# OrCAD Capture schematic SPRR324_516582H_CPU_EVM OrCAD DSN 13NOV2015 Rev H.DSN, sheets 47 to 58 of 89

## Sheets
47 SH54 - DDR3 MEMORY CAPS BANK 2: size B; rev: A
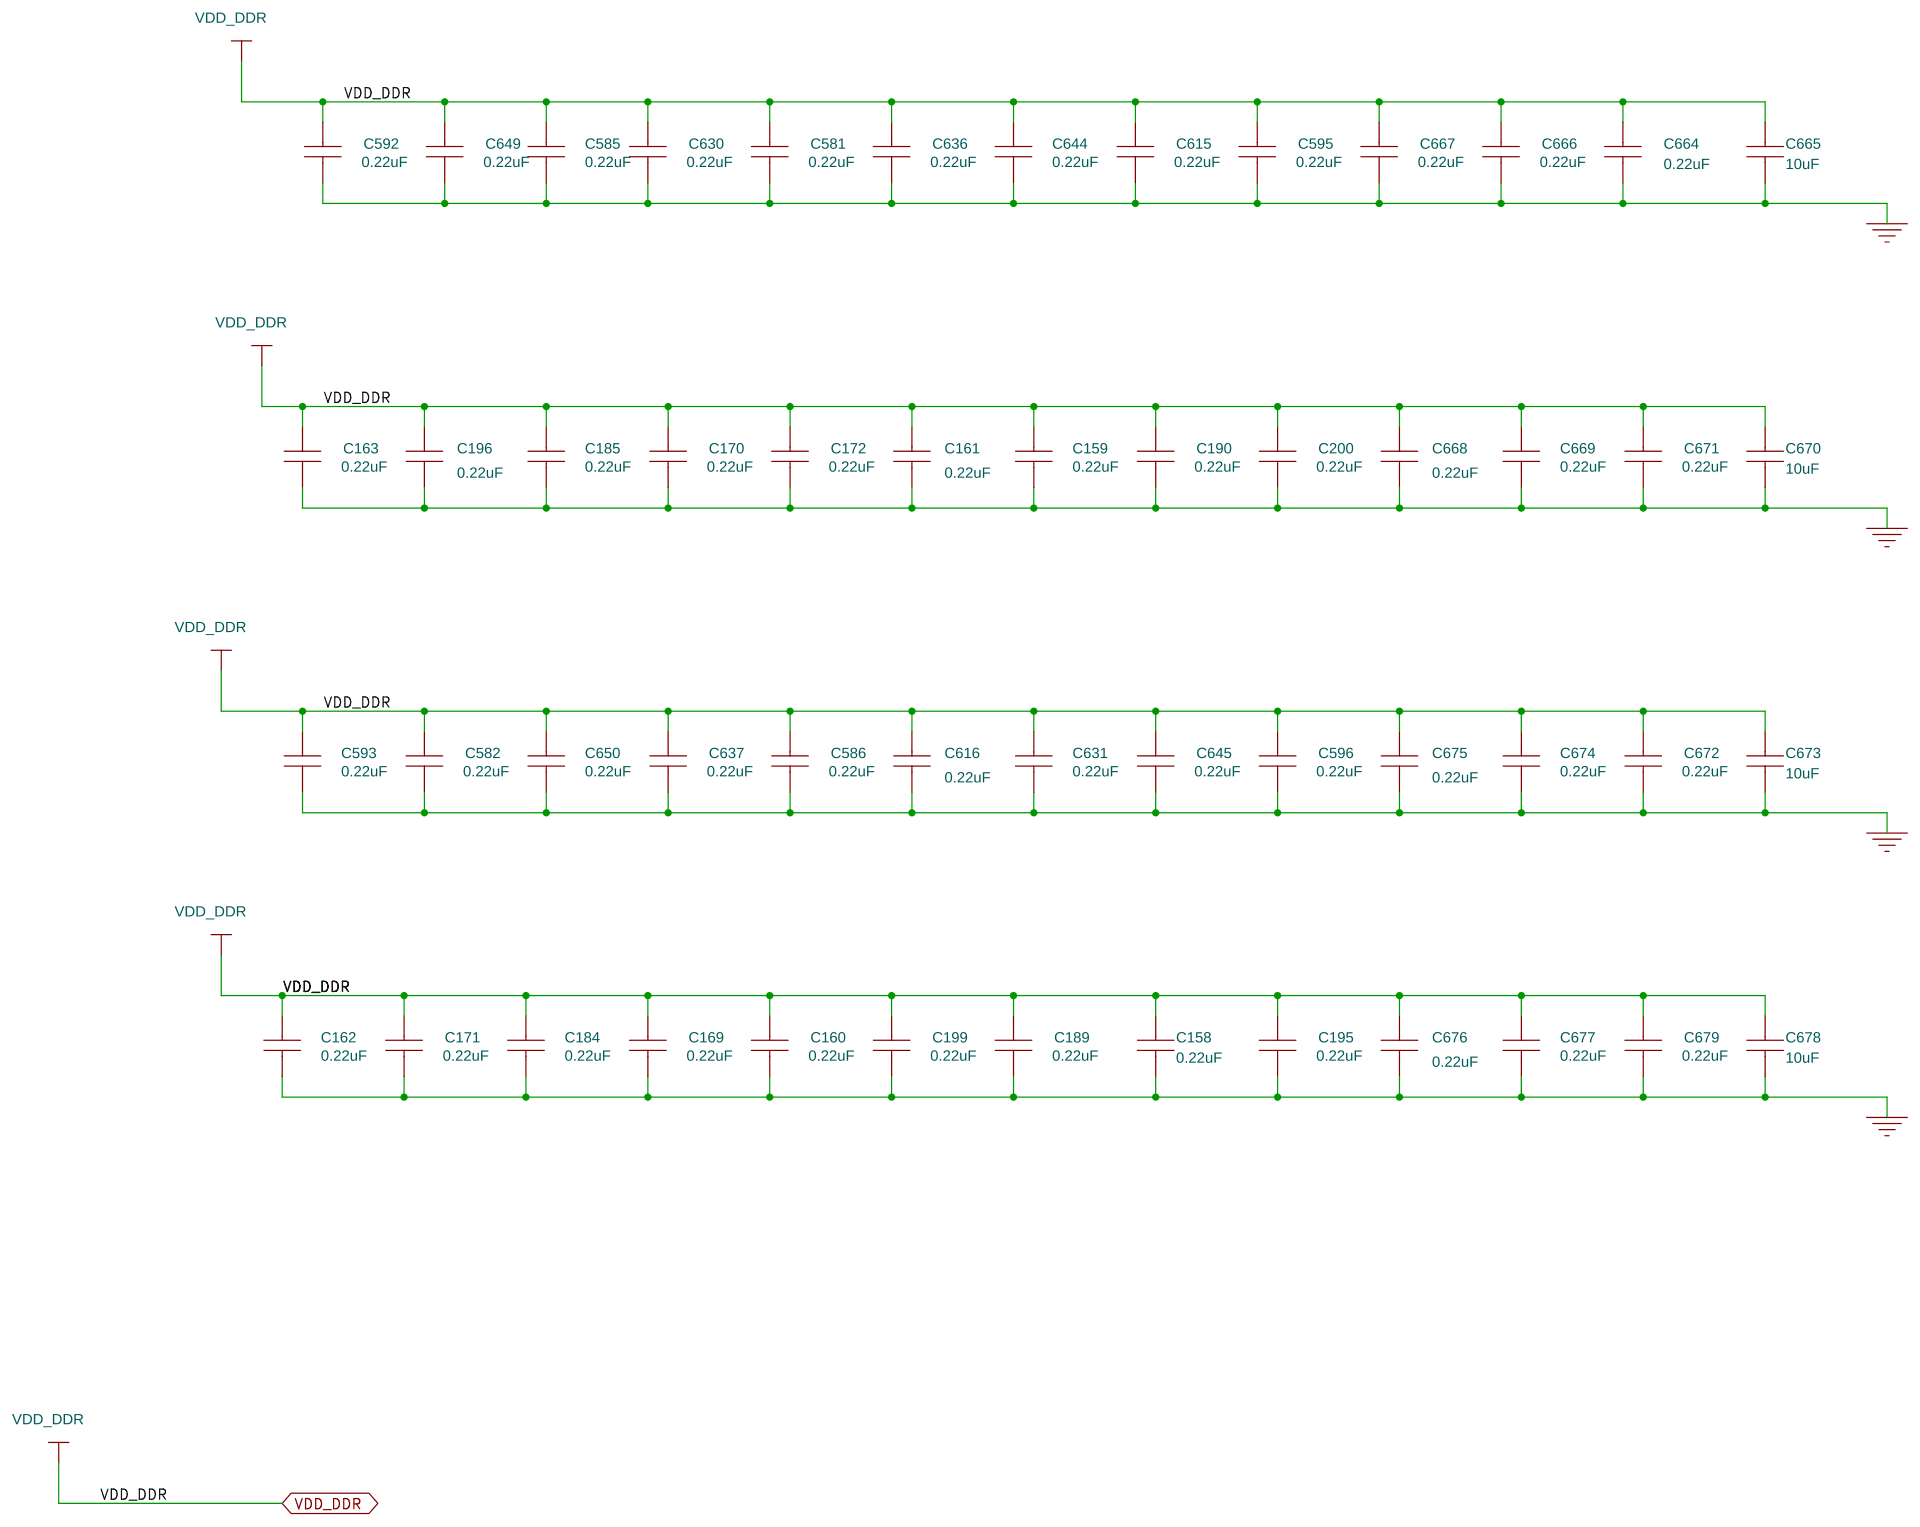
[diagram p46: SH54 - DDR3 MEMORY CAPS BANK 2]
48 SH55 - DDR TERMNATION BANK 2: size B
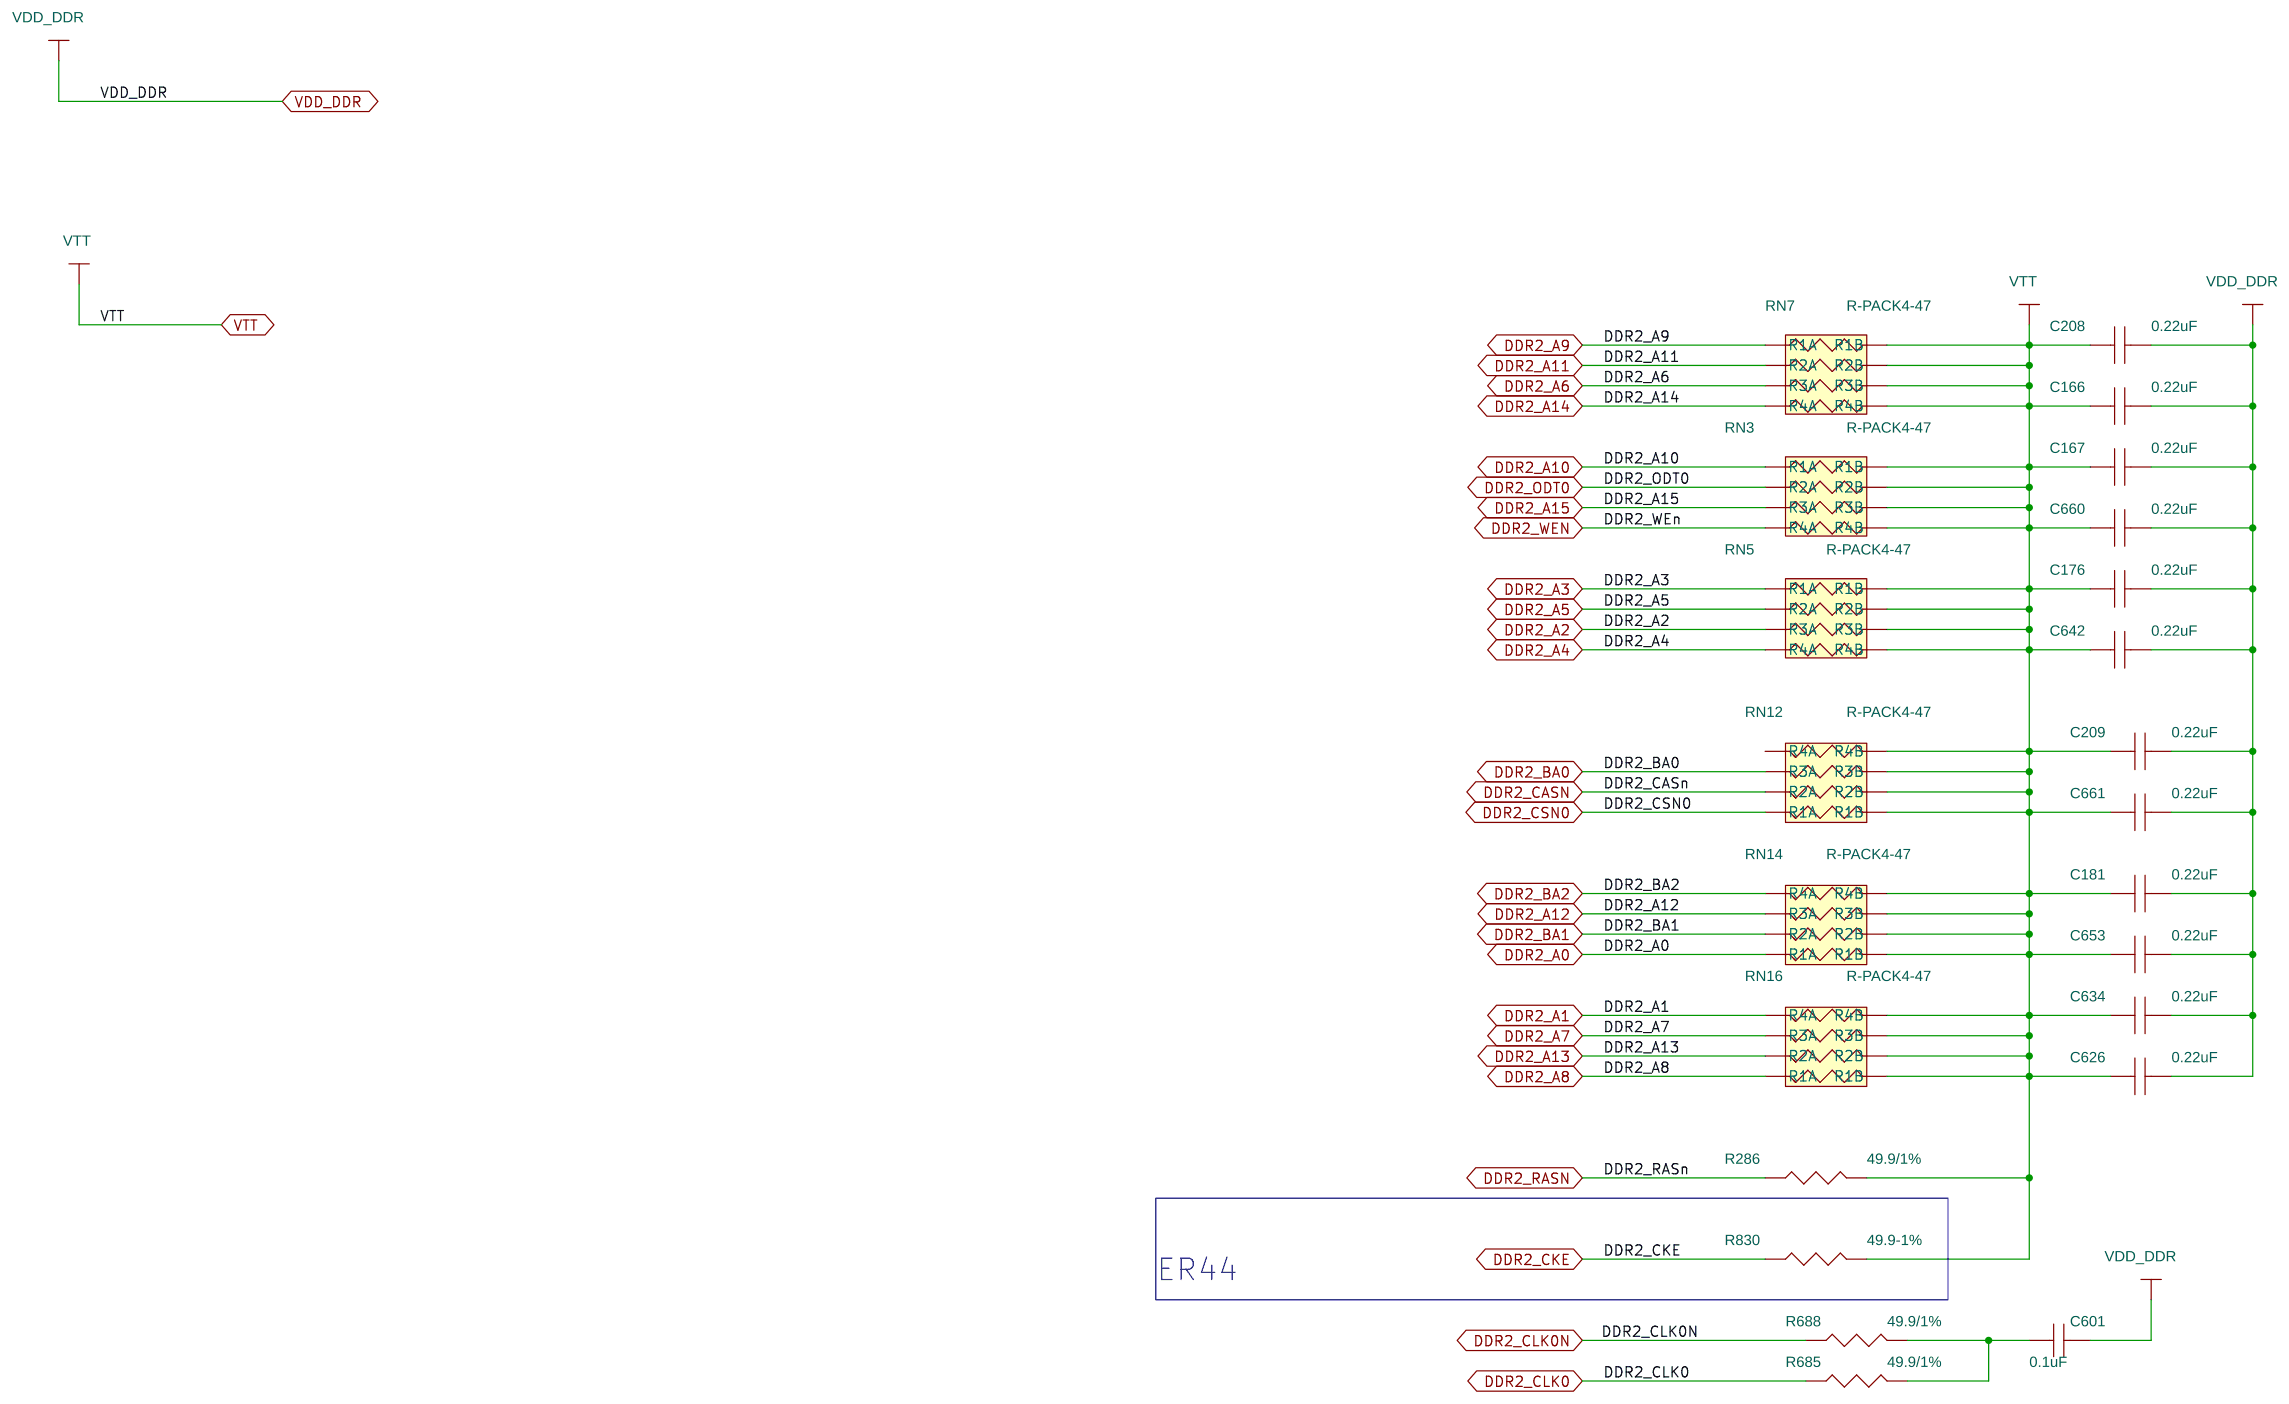
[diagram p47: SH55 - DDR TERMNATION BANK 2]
49 SH56 - USB VBUS: size B; rev: C
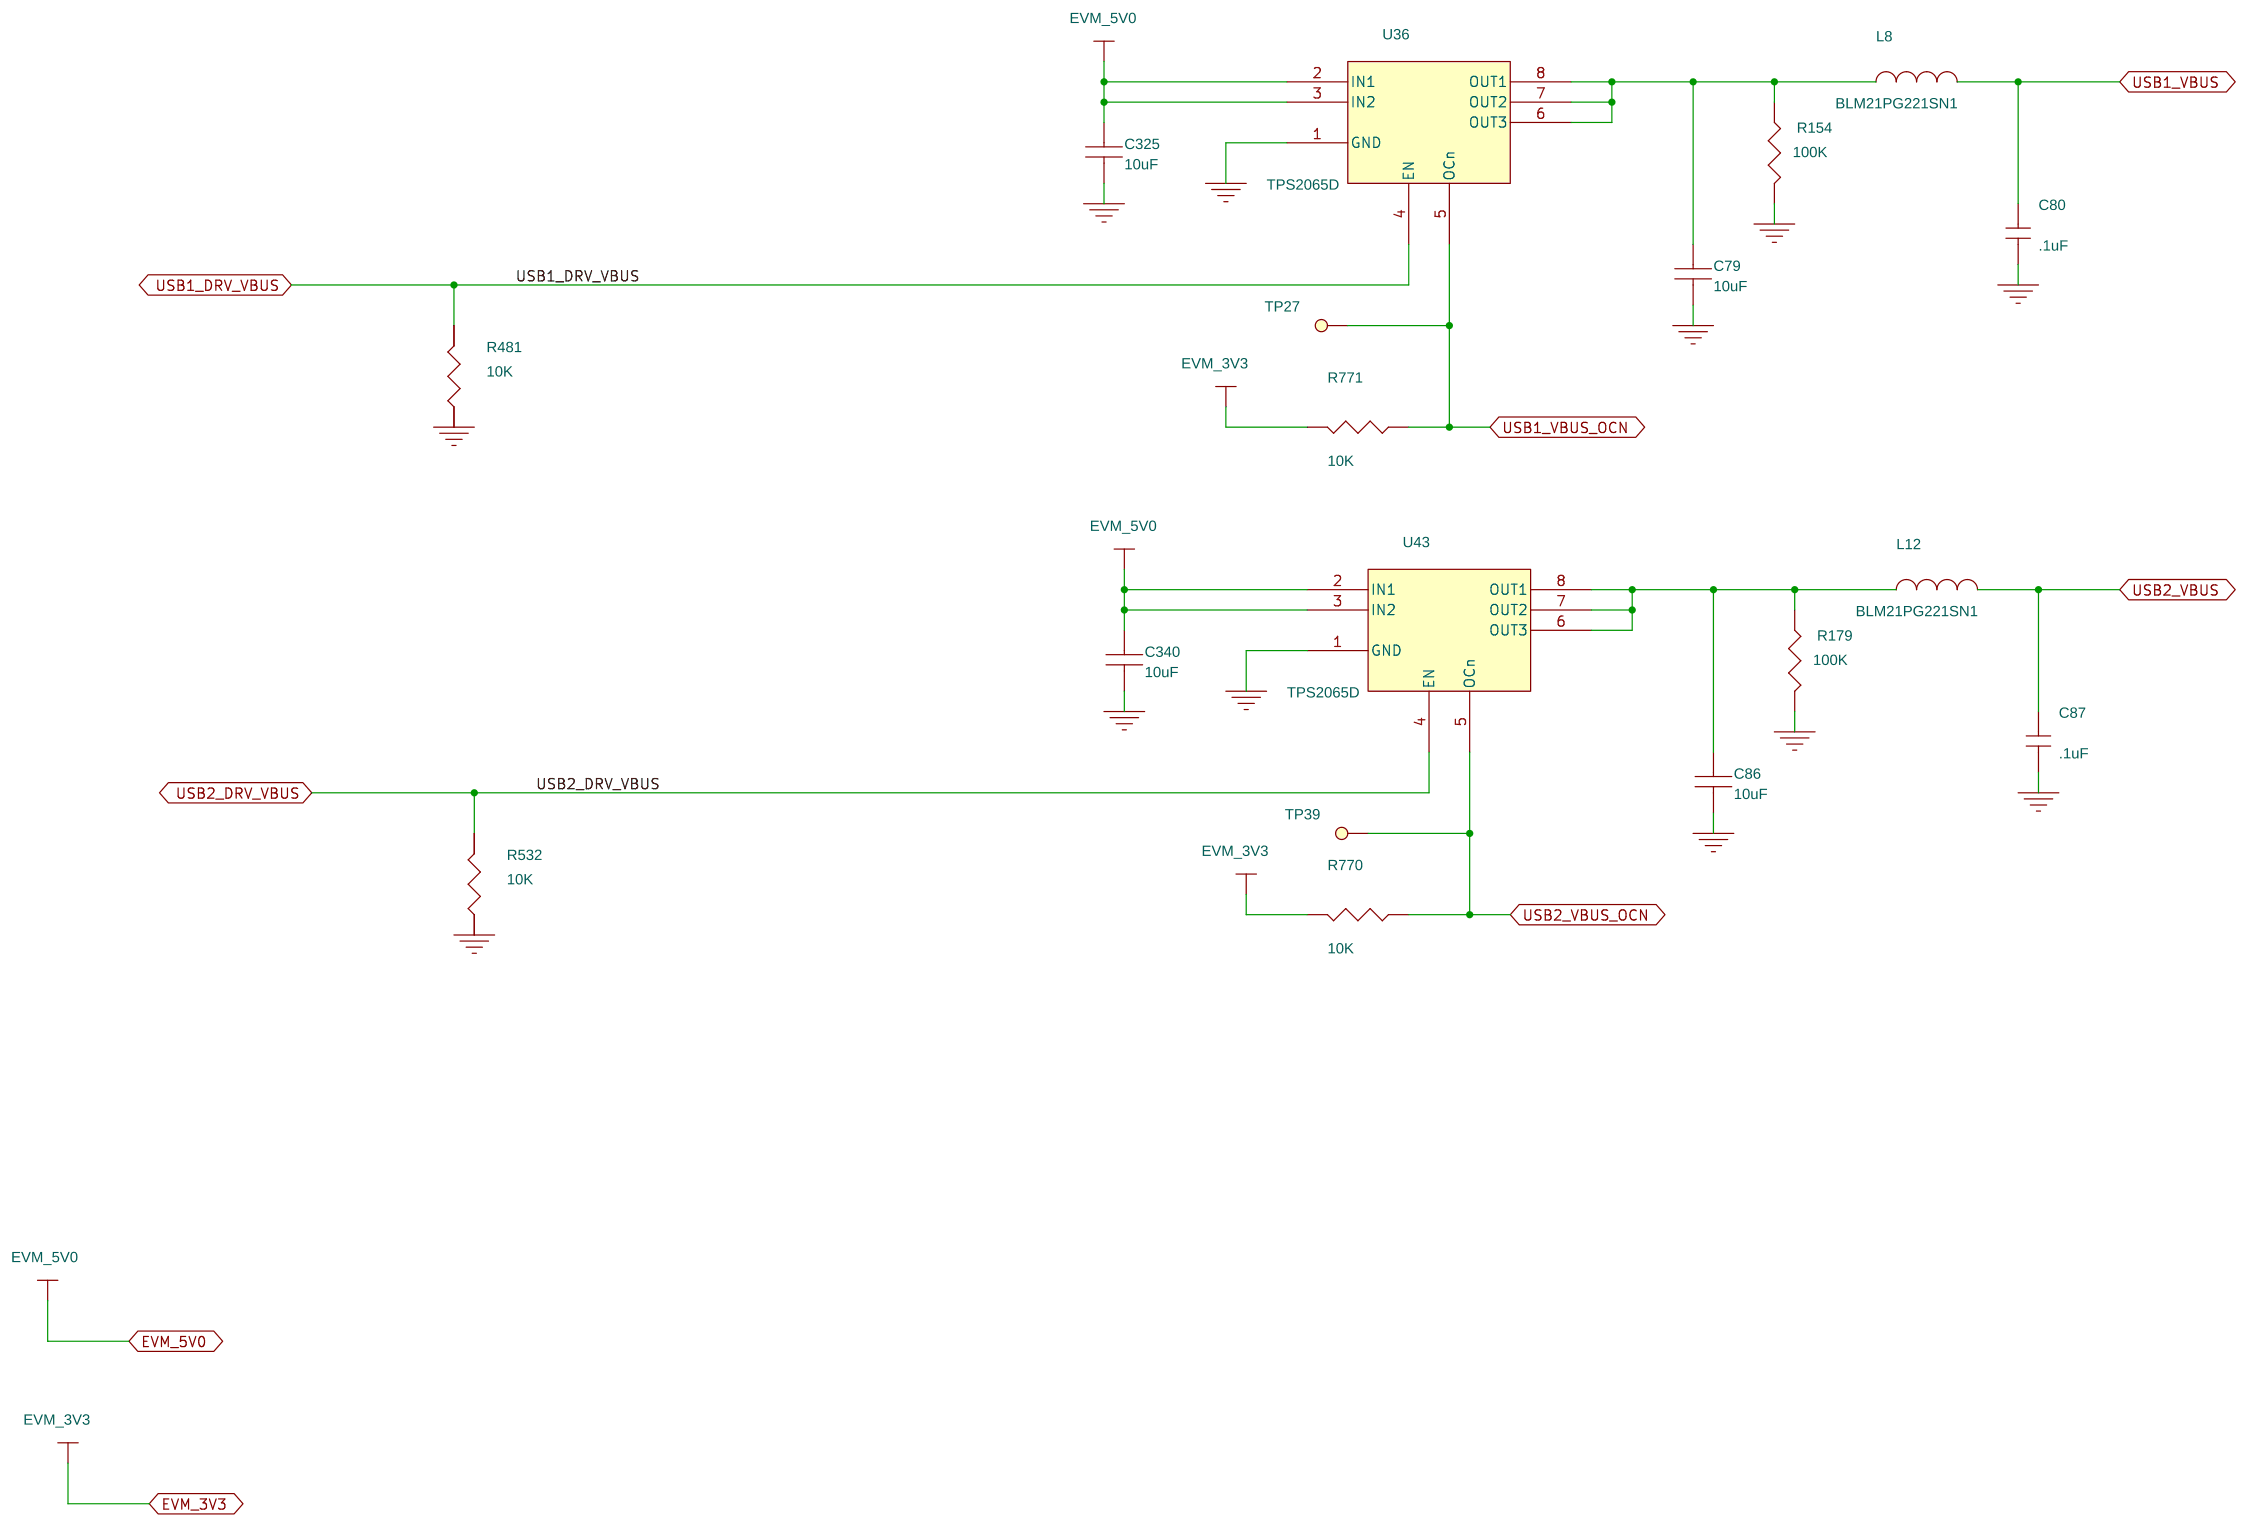
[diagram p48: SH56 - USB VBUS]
50 SH57 - USB CONNECTORS: size B; rev: F
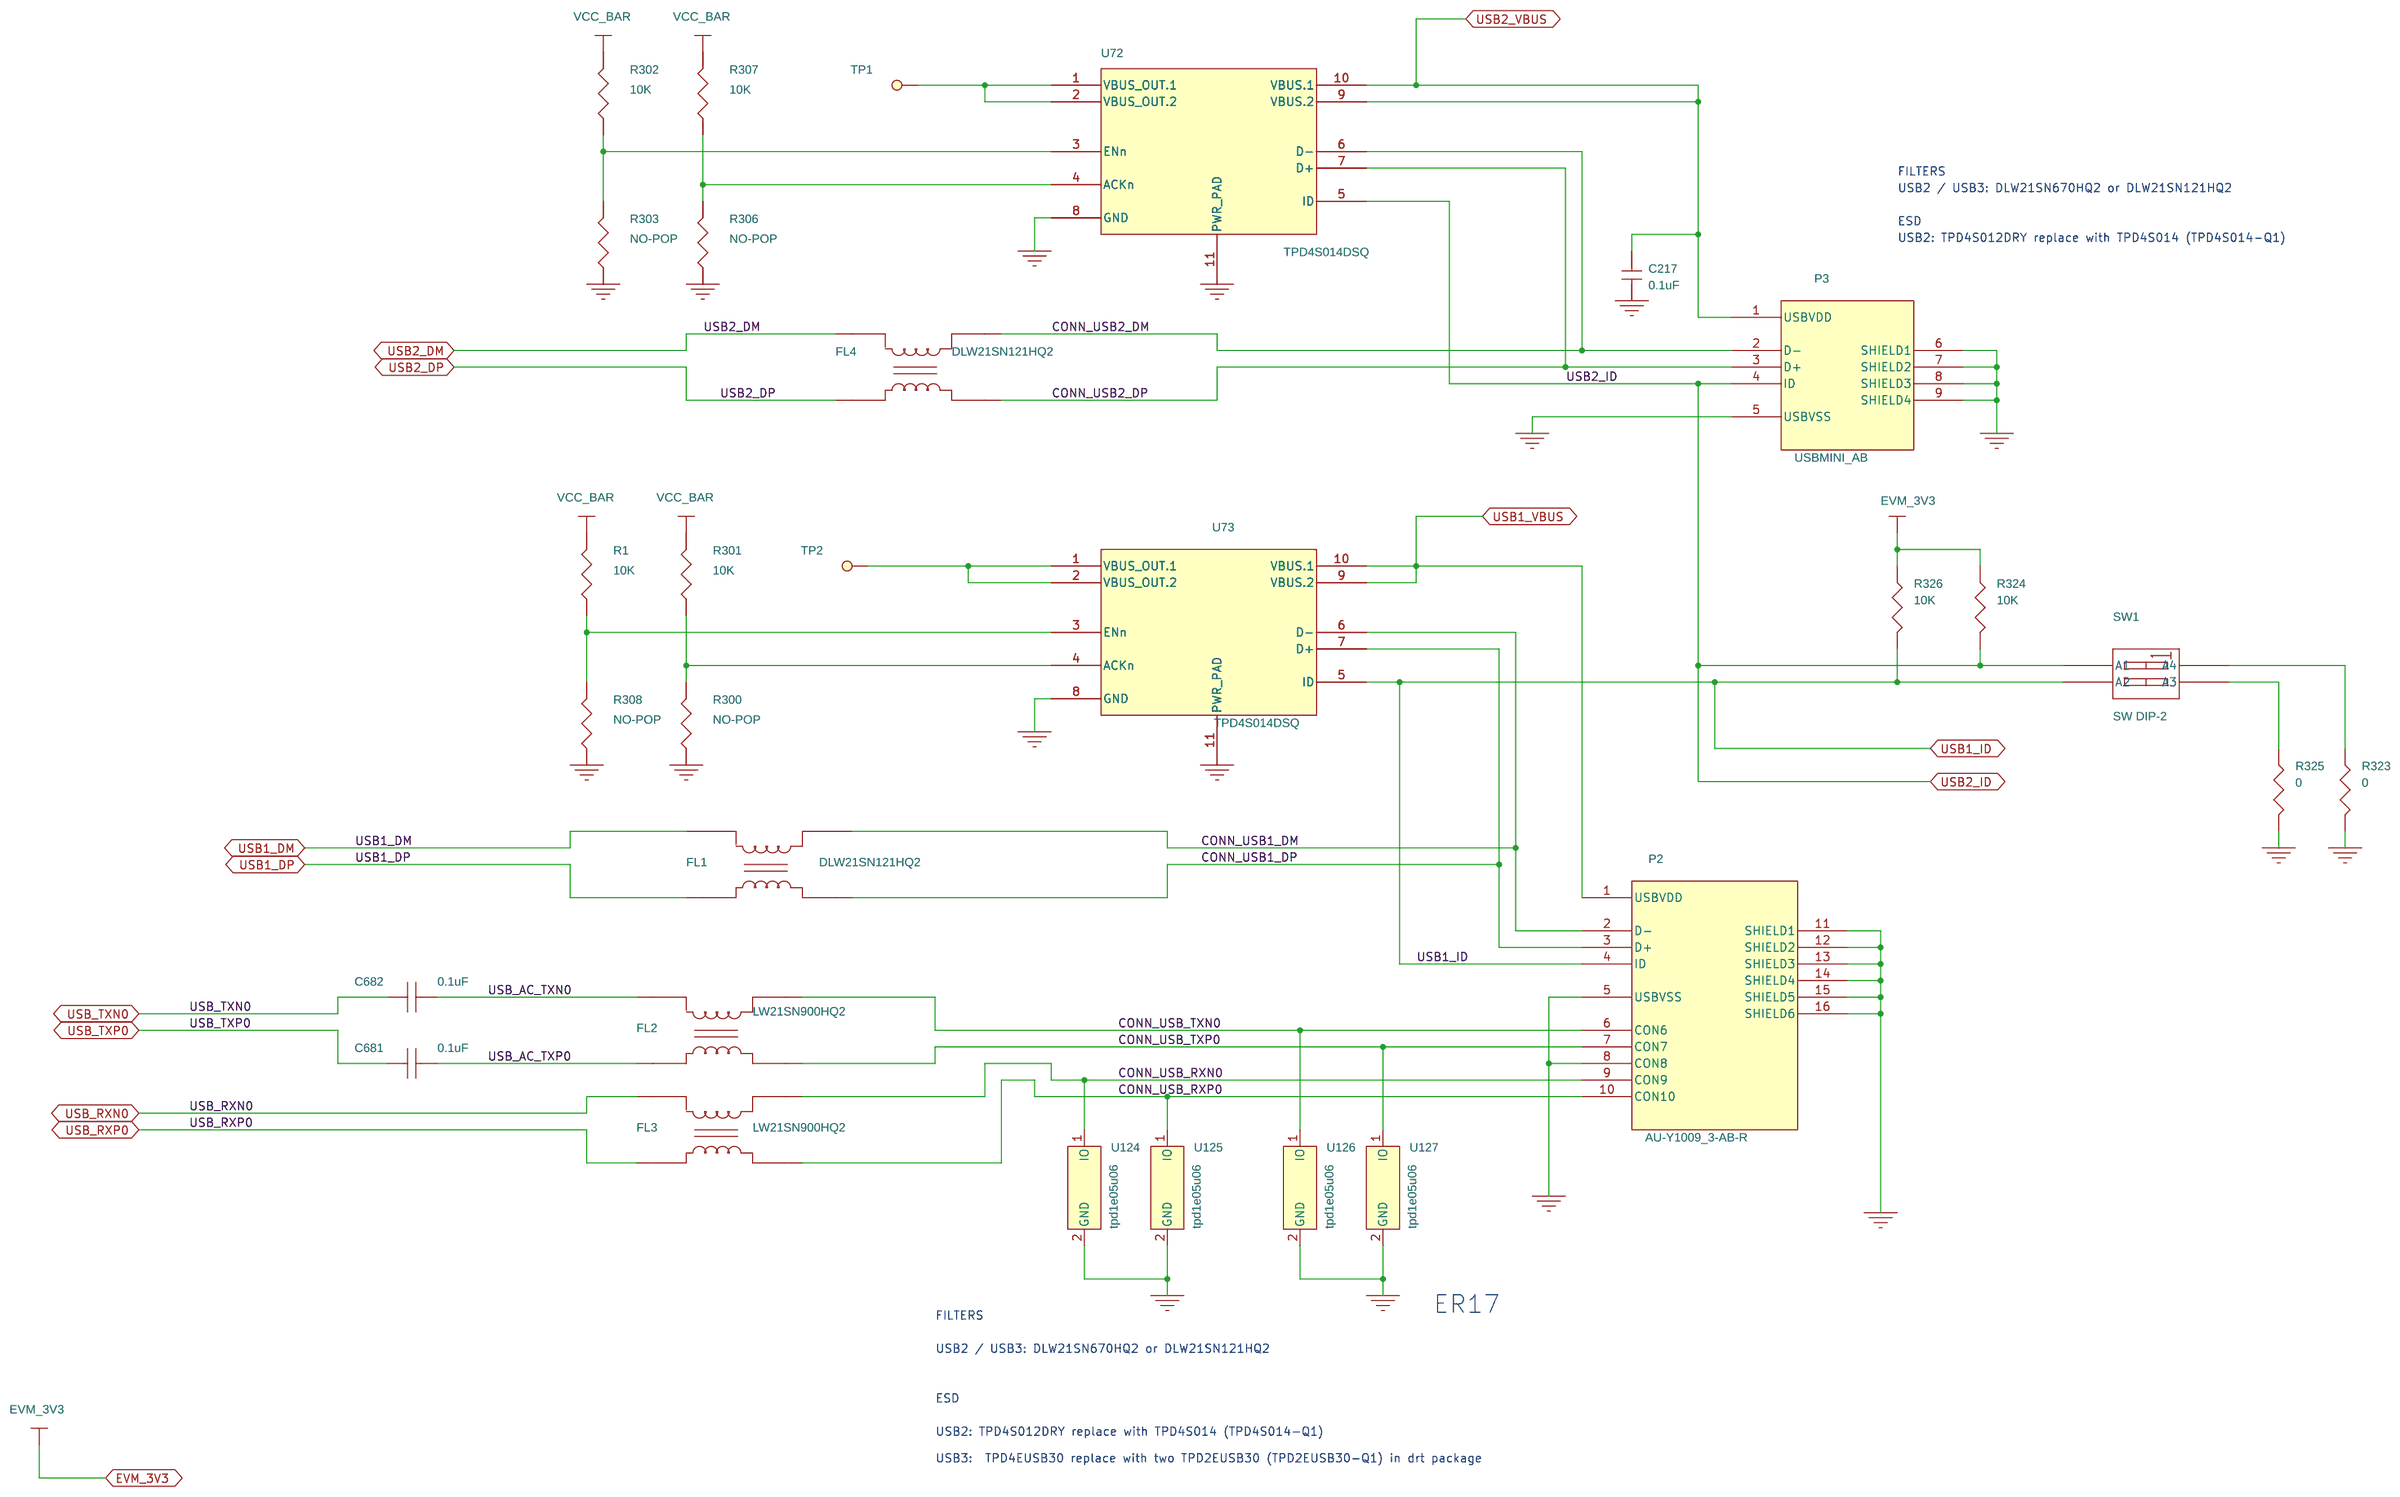
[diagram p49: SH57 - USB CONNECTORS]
51 SH58 - FTDI UART: size B; rev: D
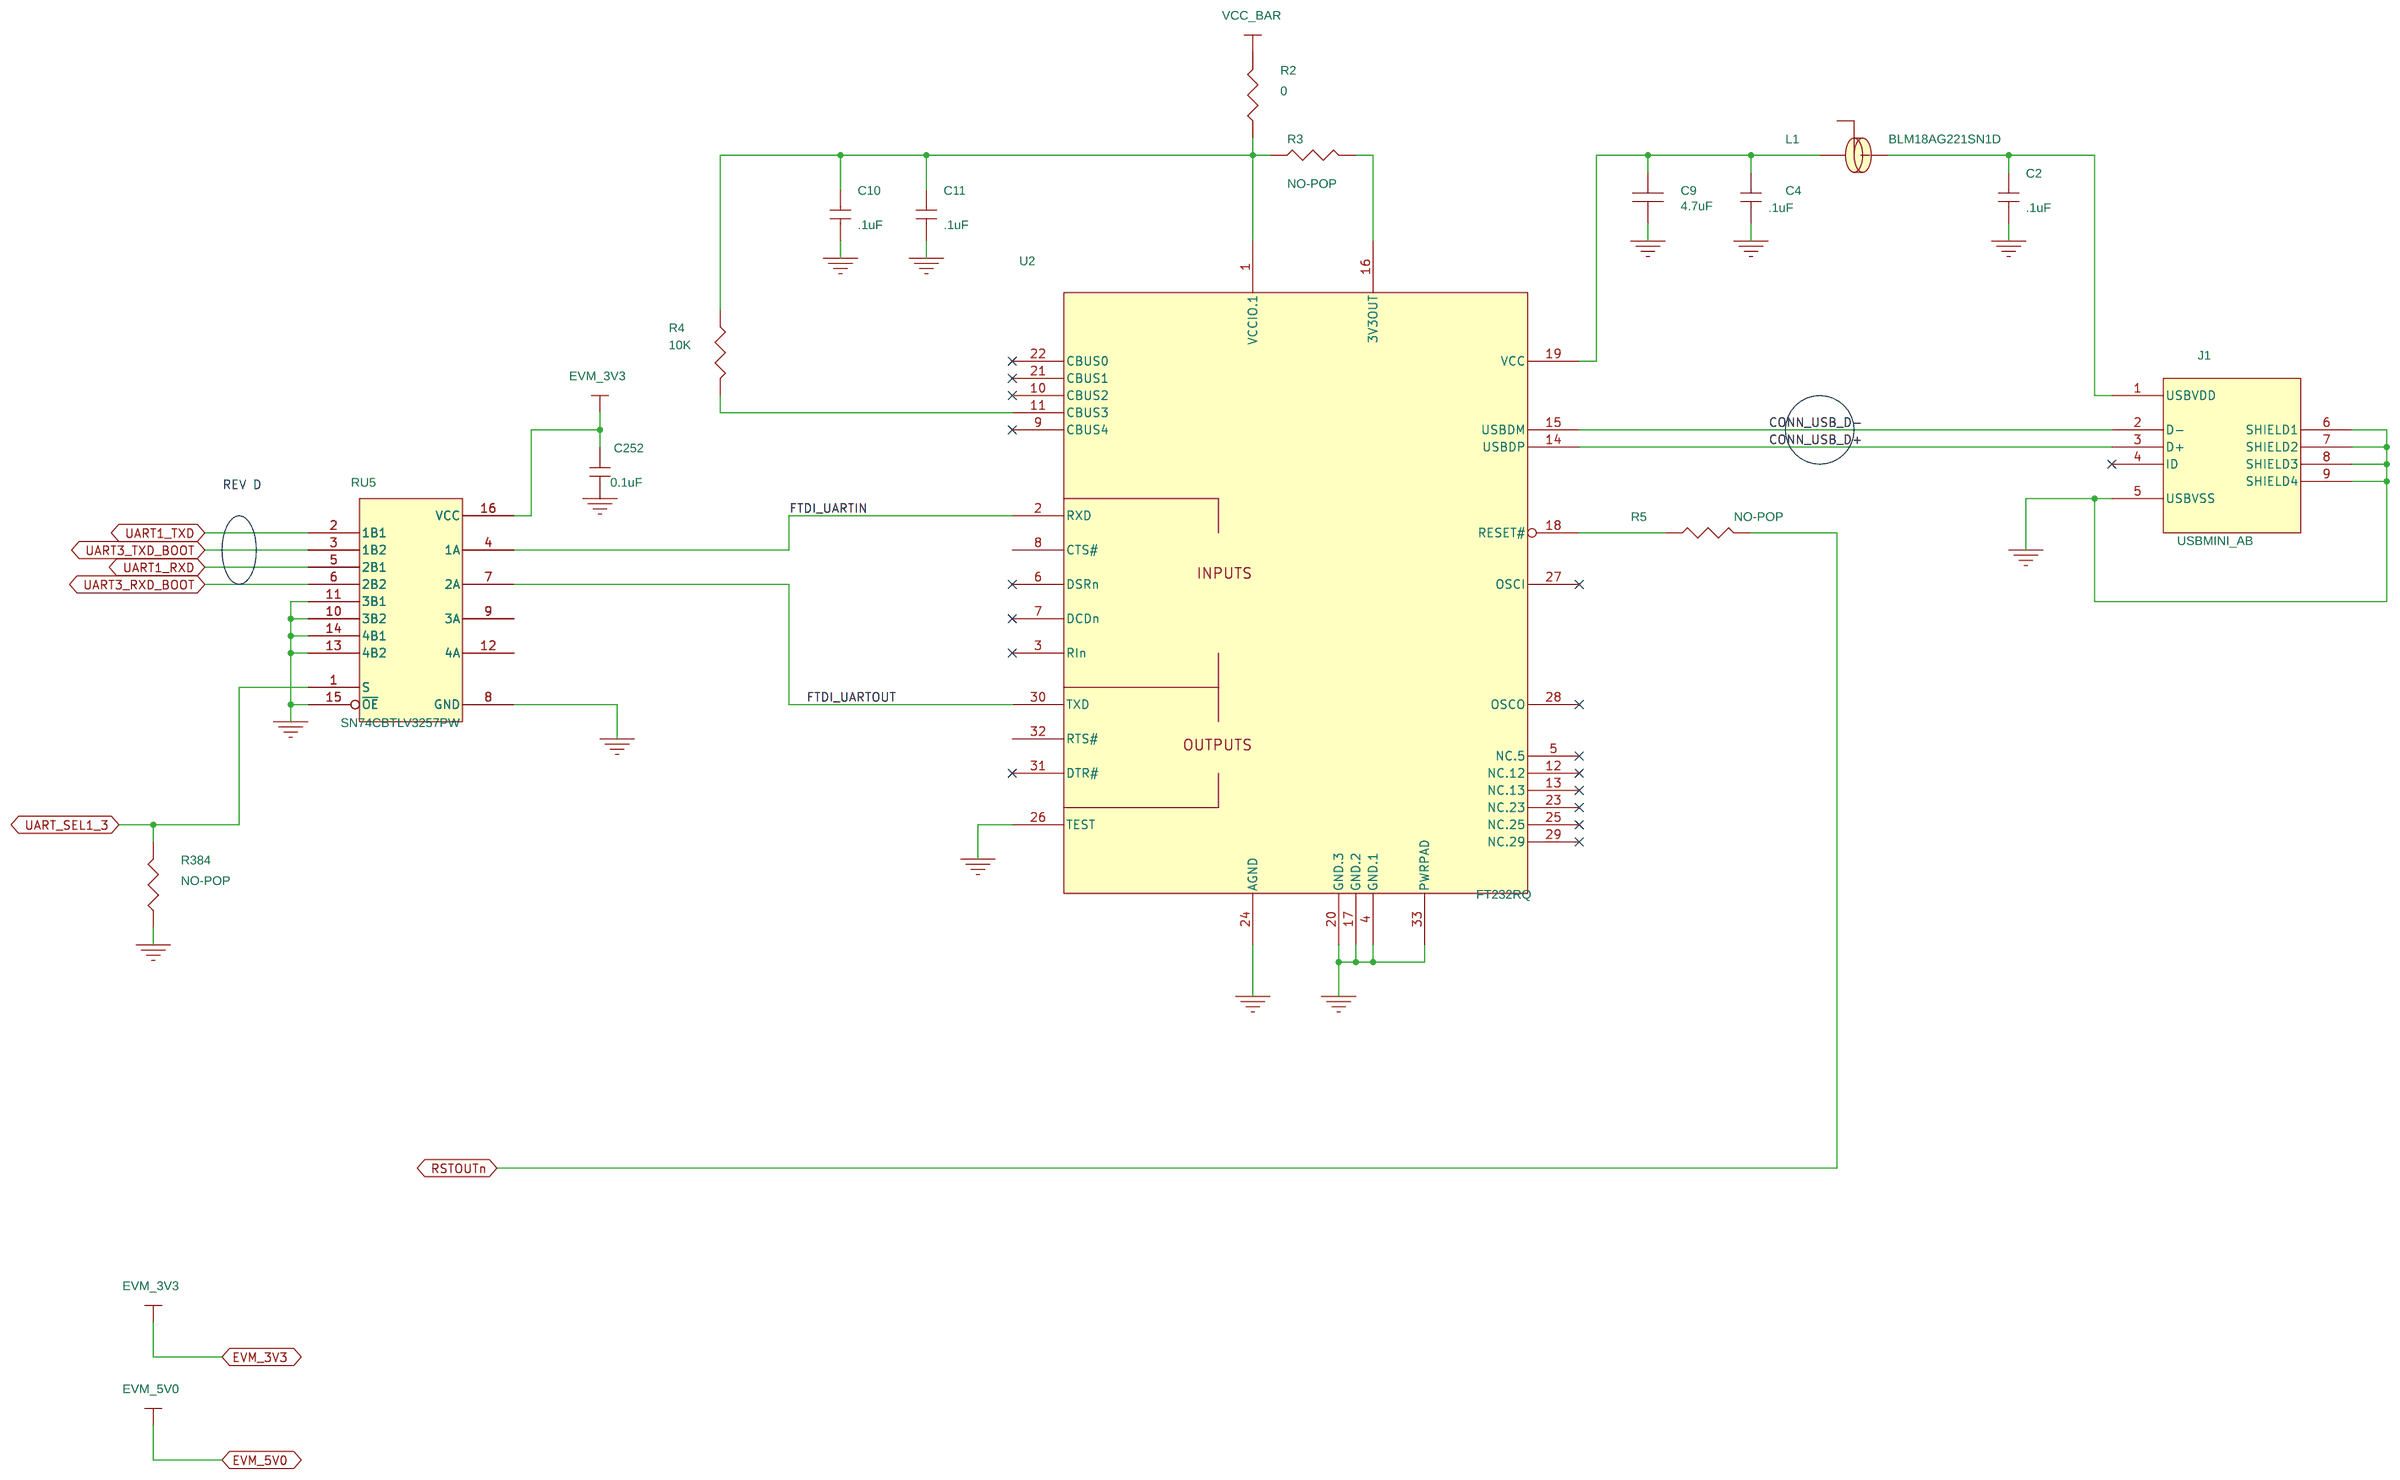
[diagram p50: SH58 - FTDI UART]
52 SH59 - COM8 LEVEL TRANSLATOR: size B; rev: A
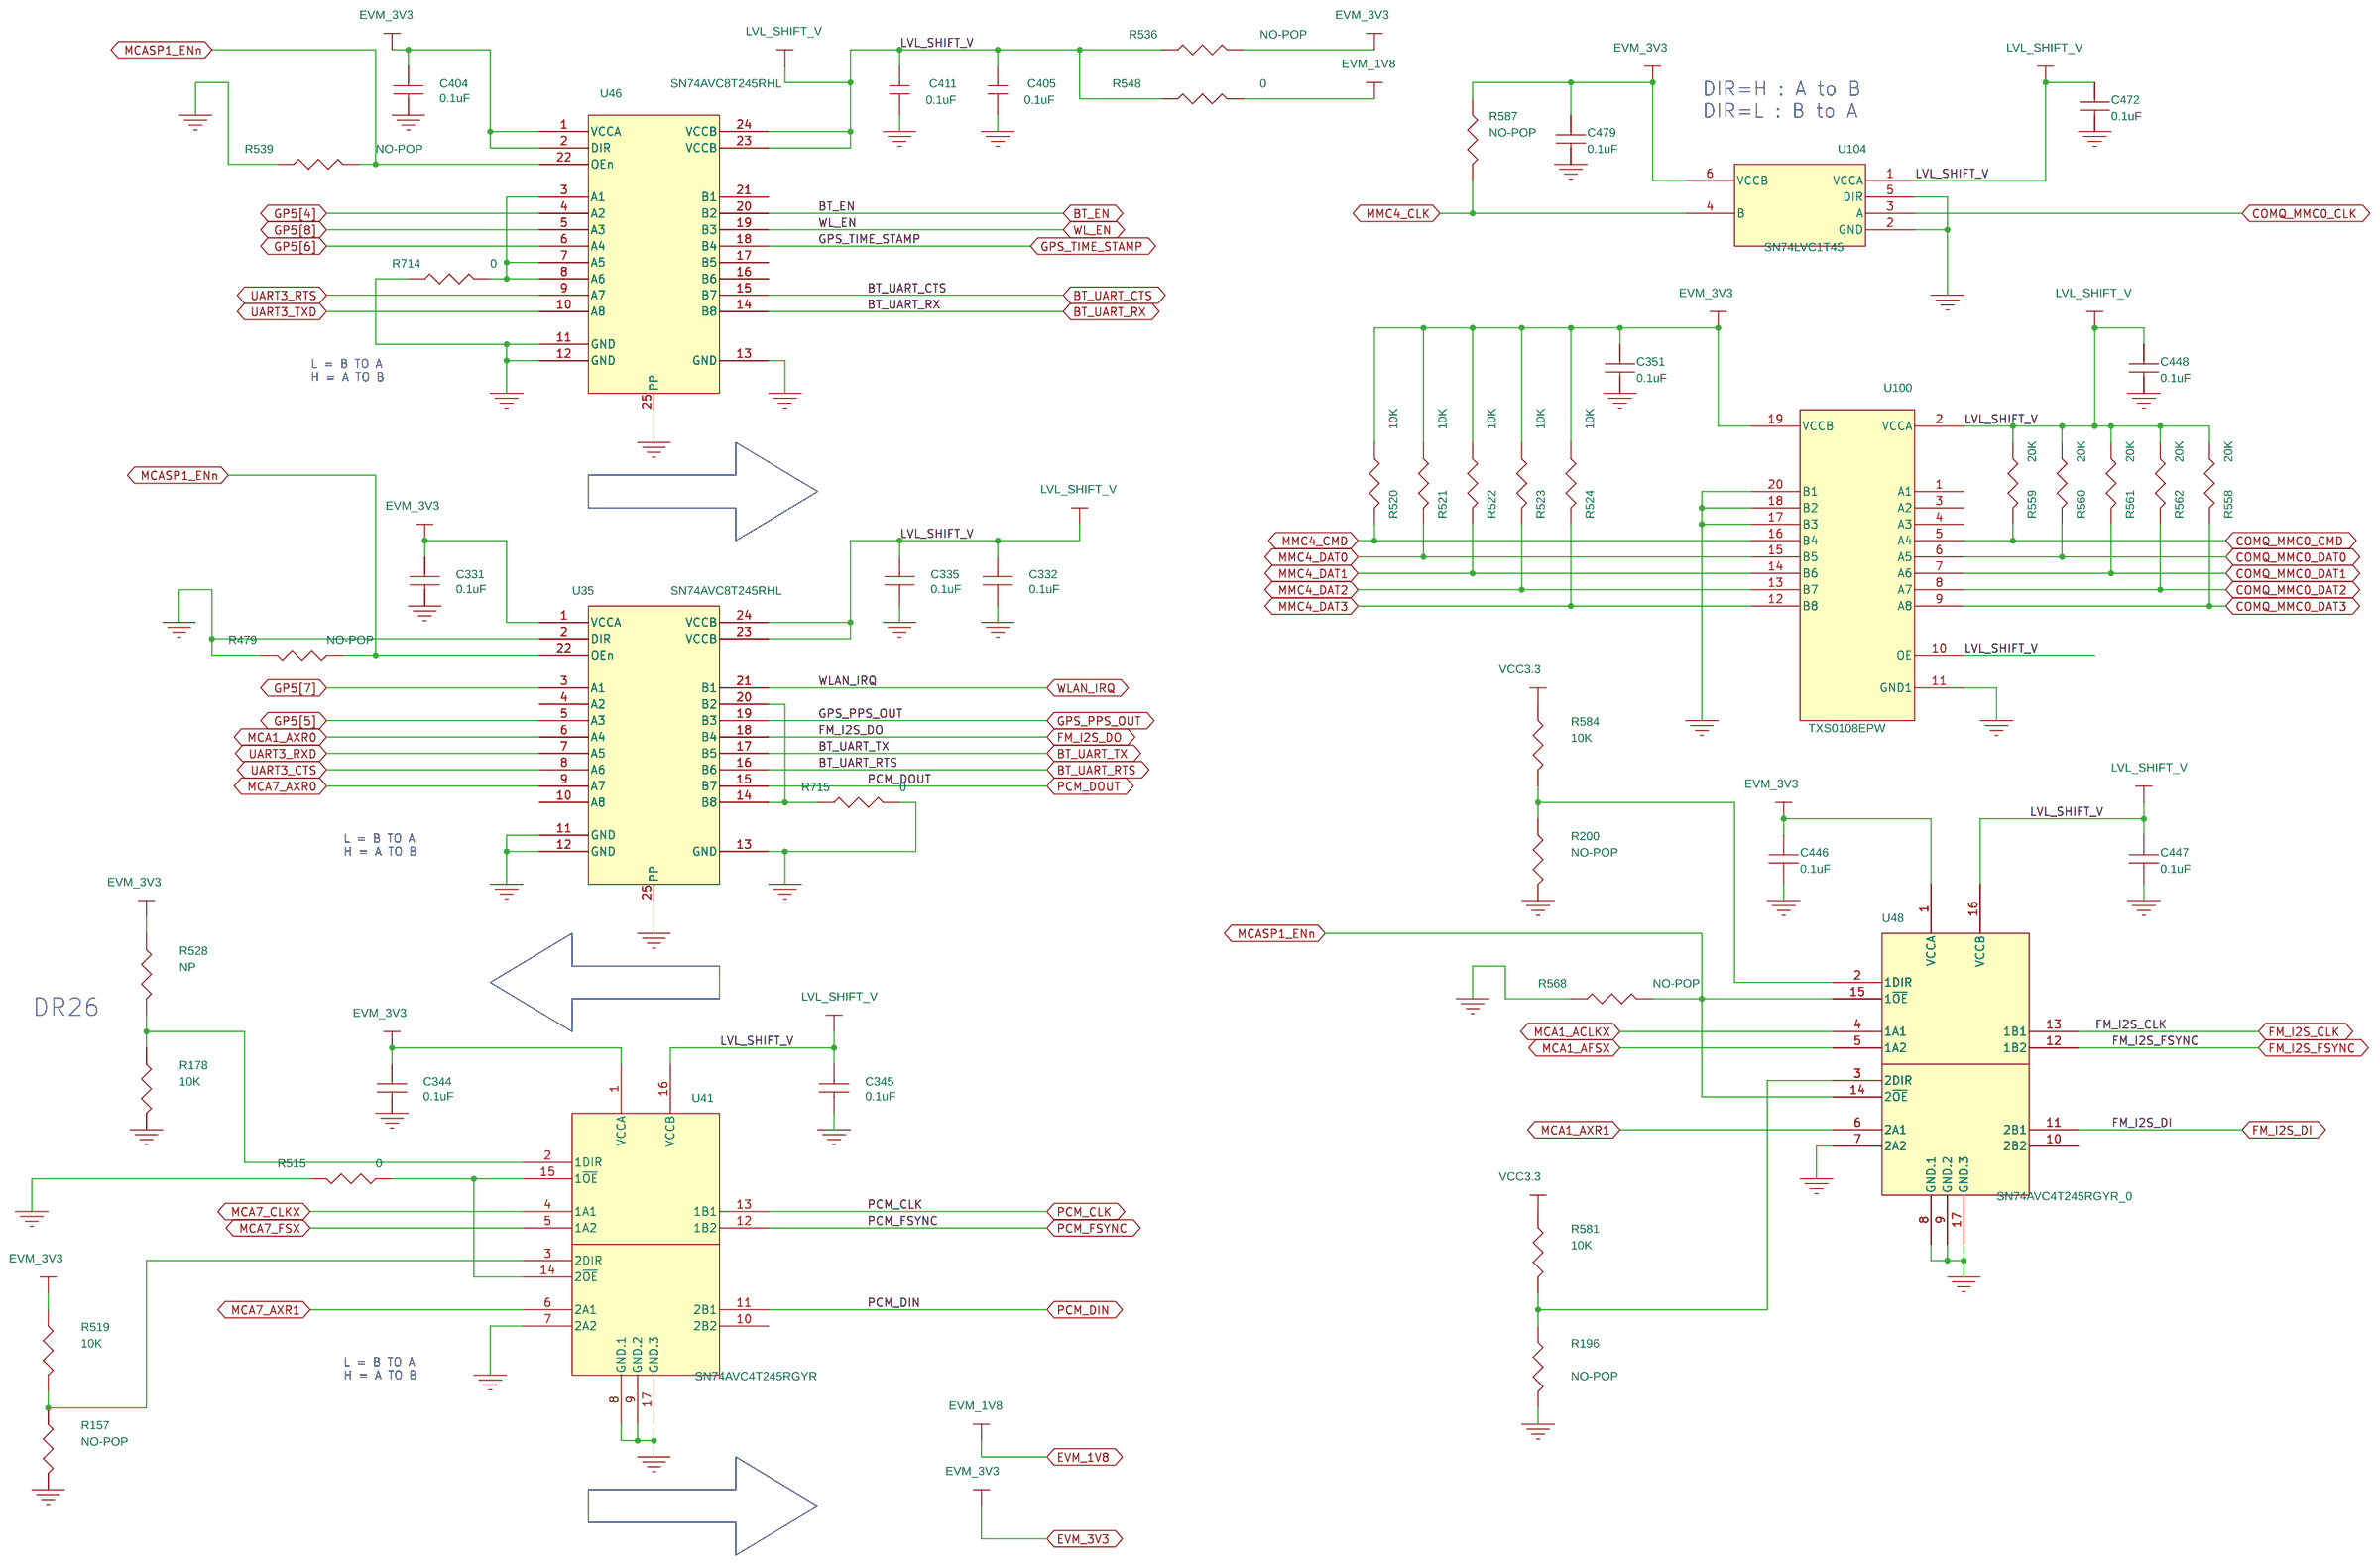
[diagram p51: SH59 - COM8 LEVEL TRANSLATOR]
53 SH60 - COM8 CONNECTOR: size B; rev: A
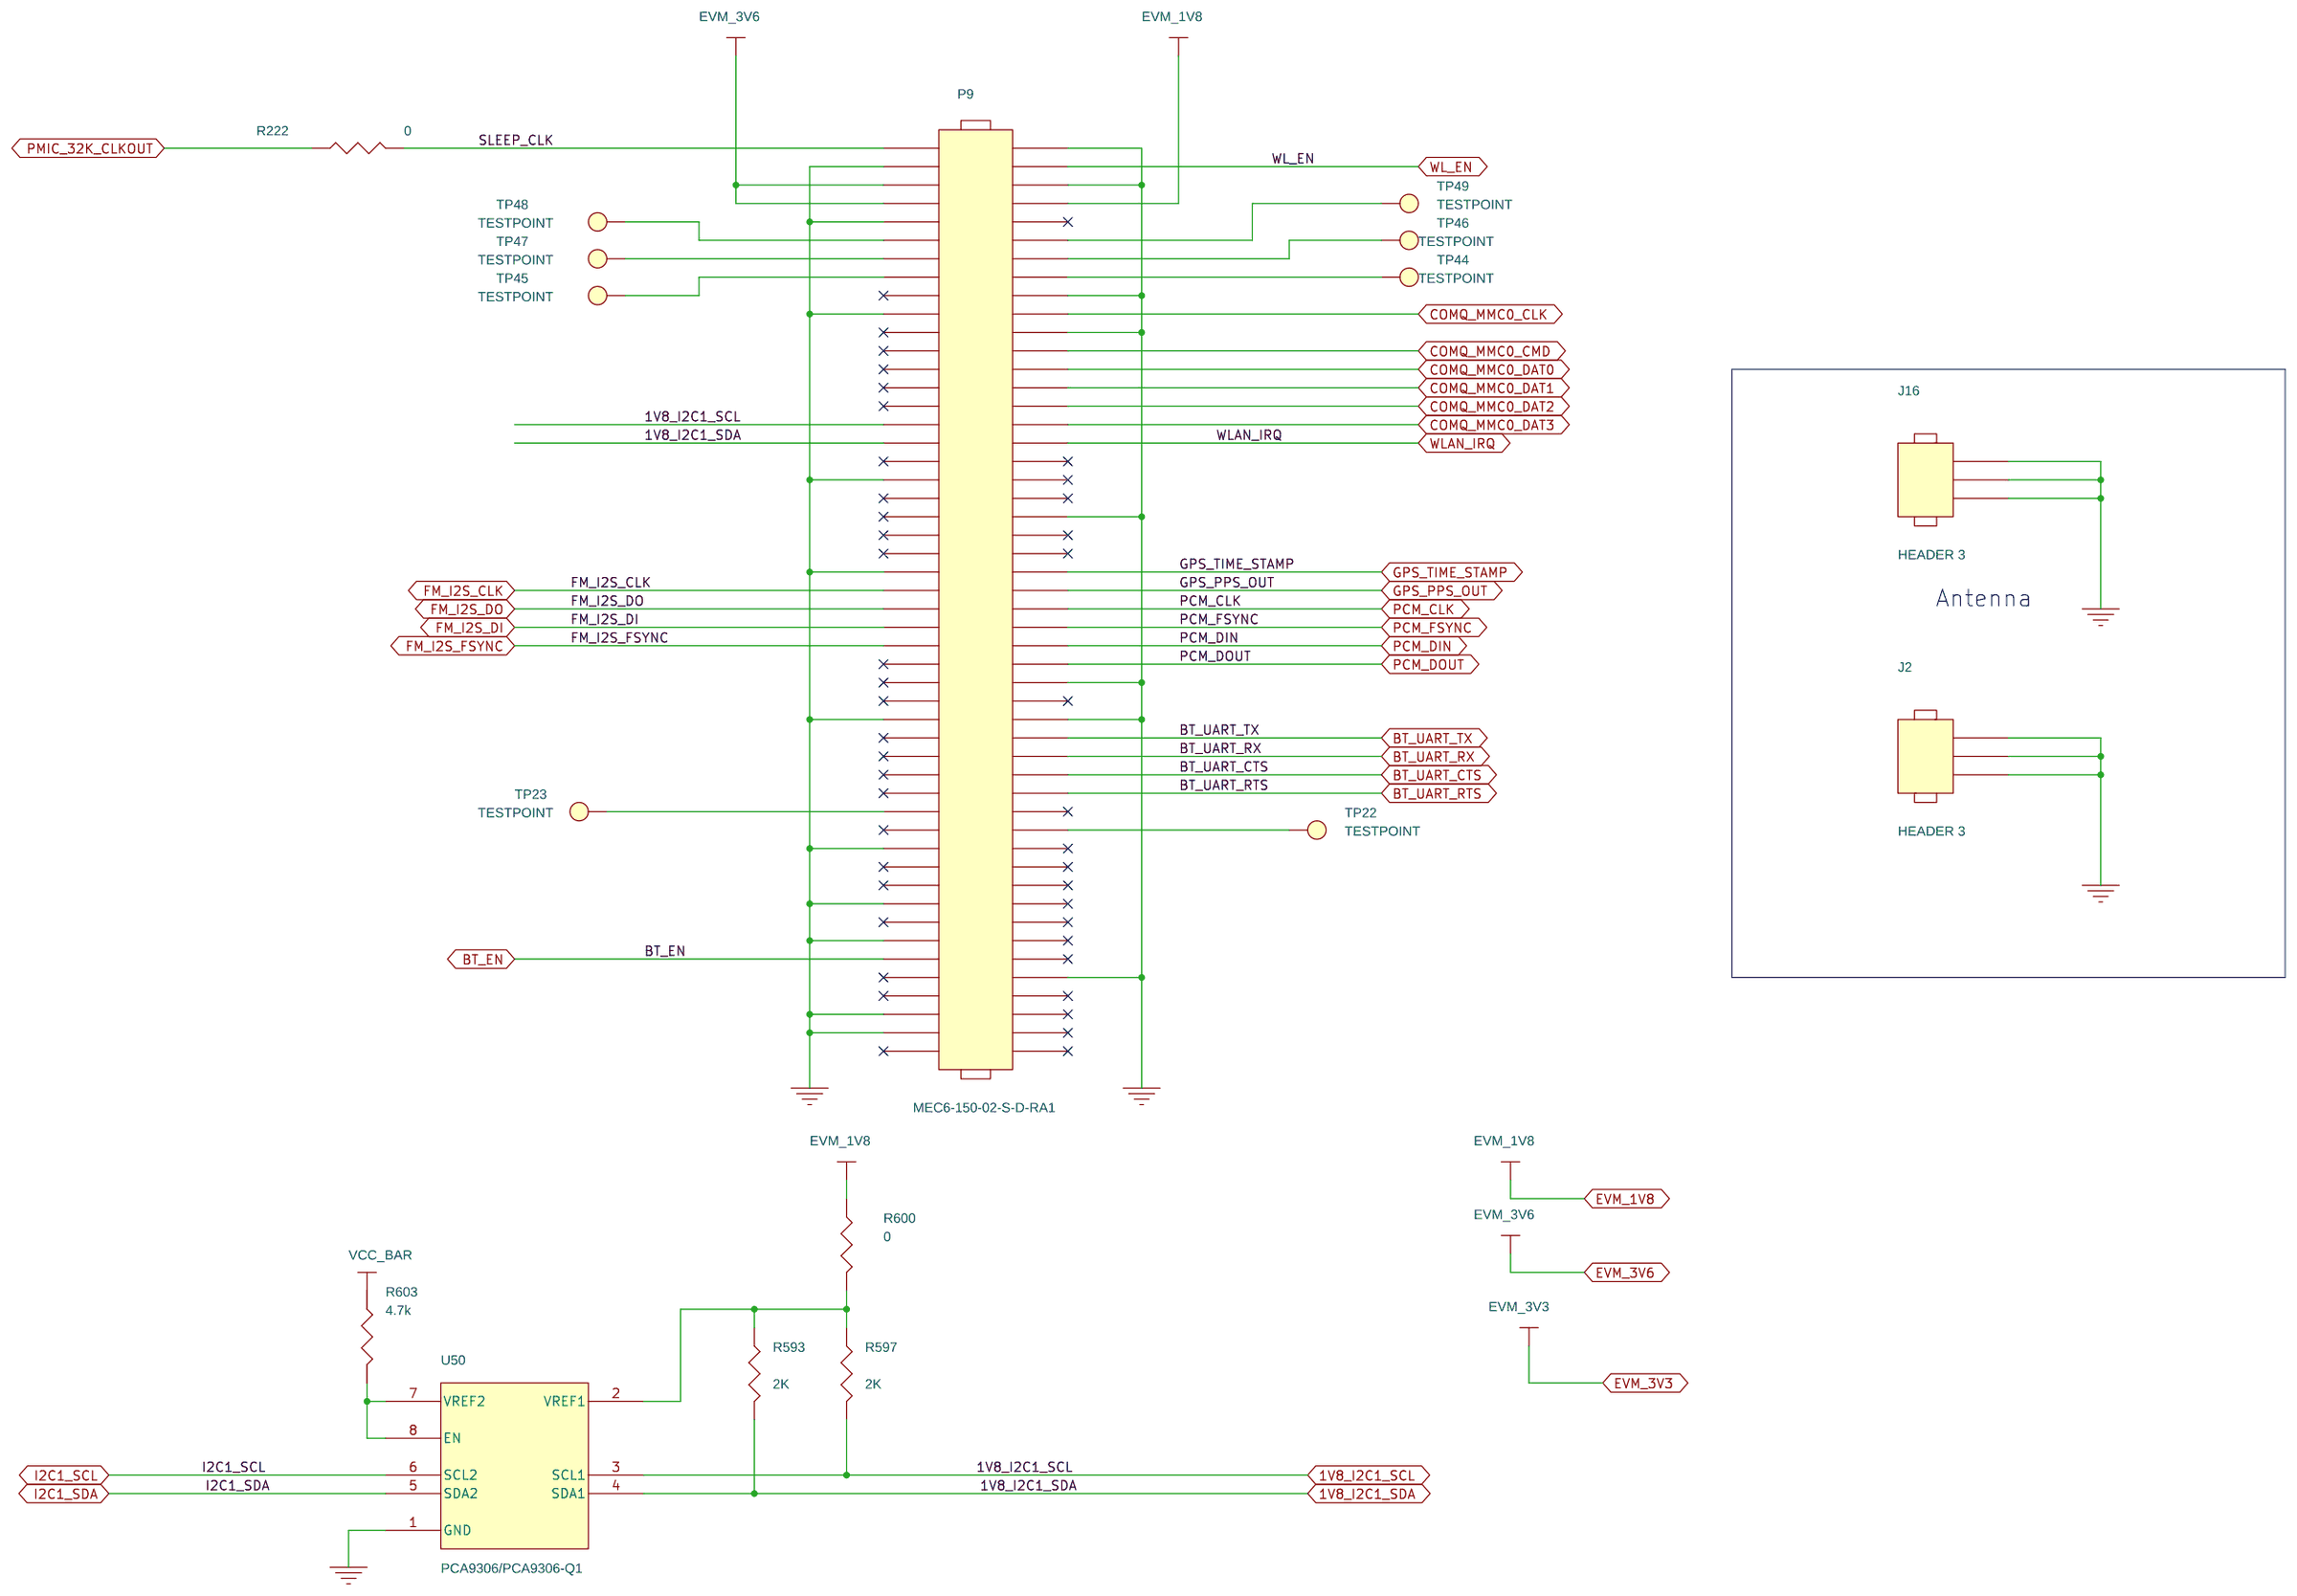
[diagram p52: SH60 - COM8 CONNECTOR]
54 SH61 - COM8 POWER: size B; rev: D
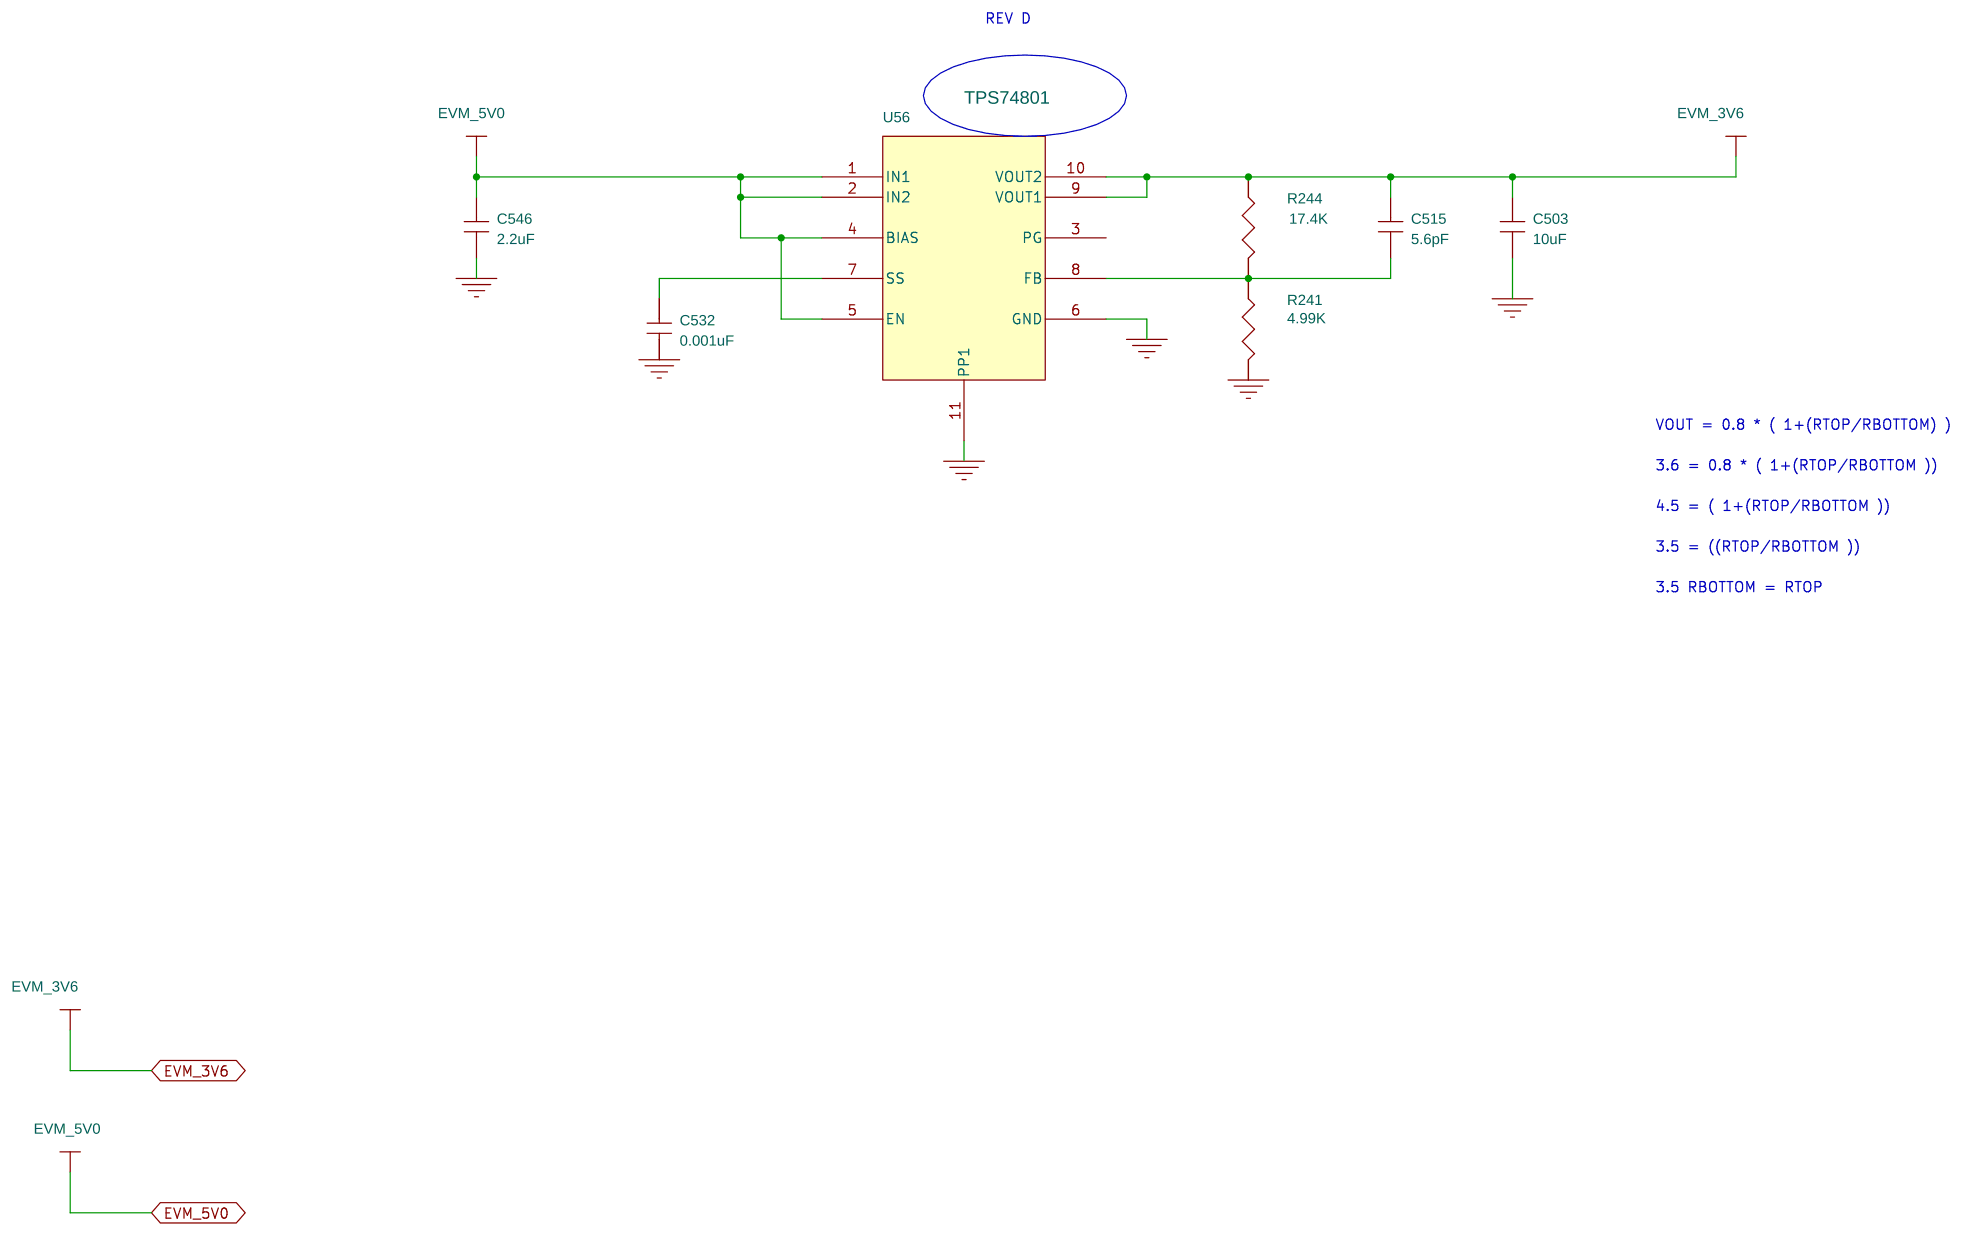
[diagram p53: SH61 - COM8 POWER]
55 SH62 - AIC3106: size B; rev: F
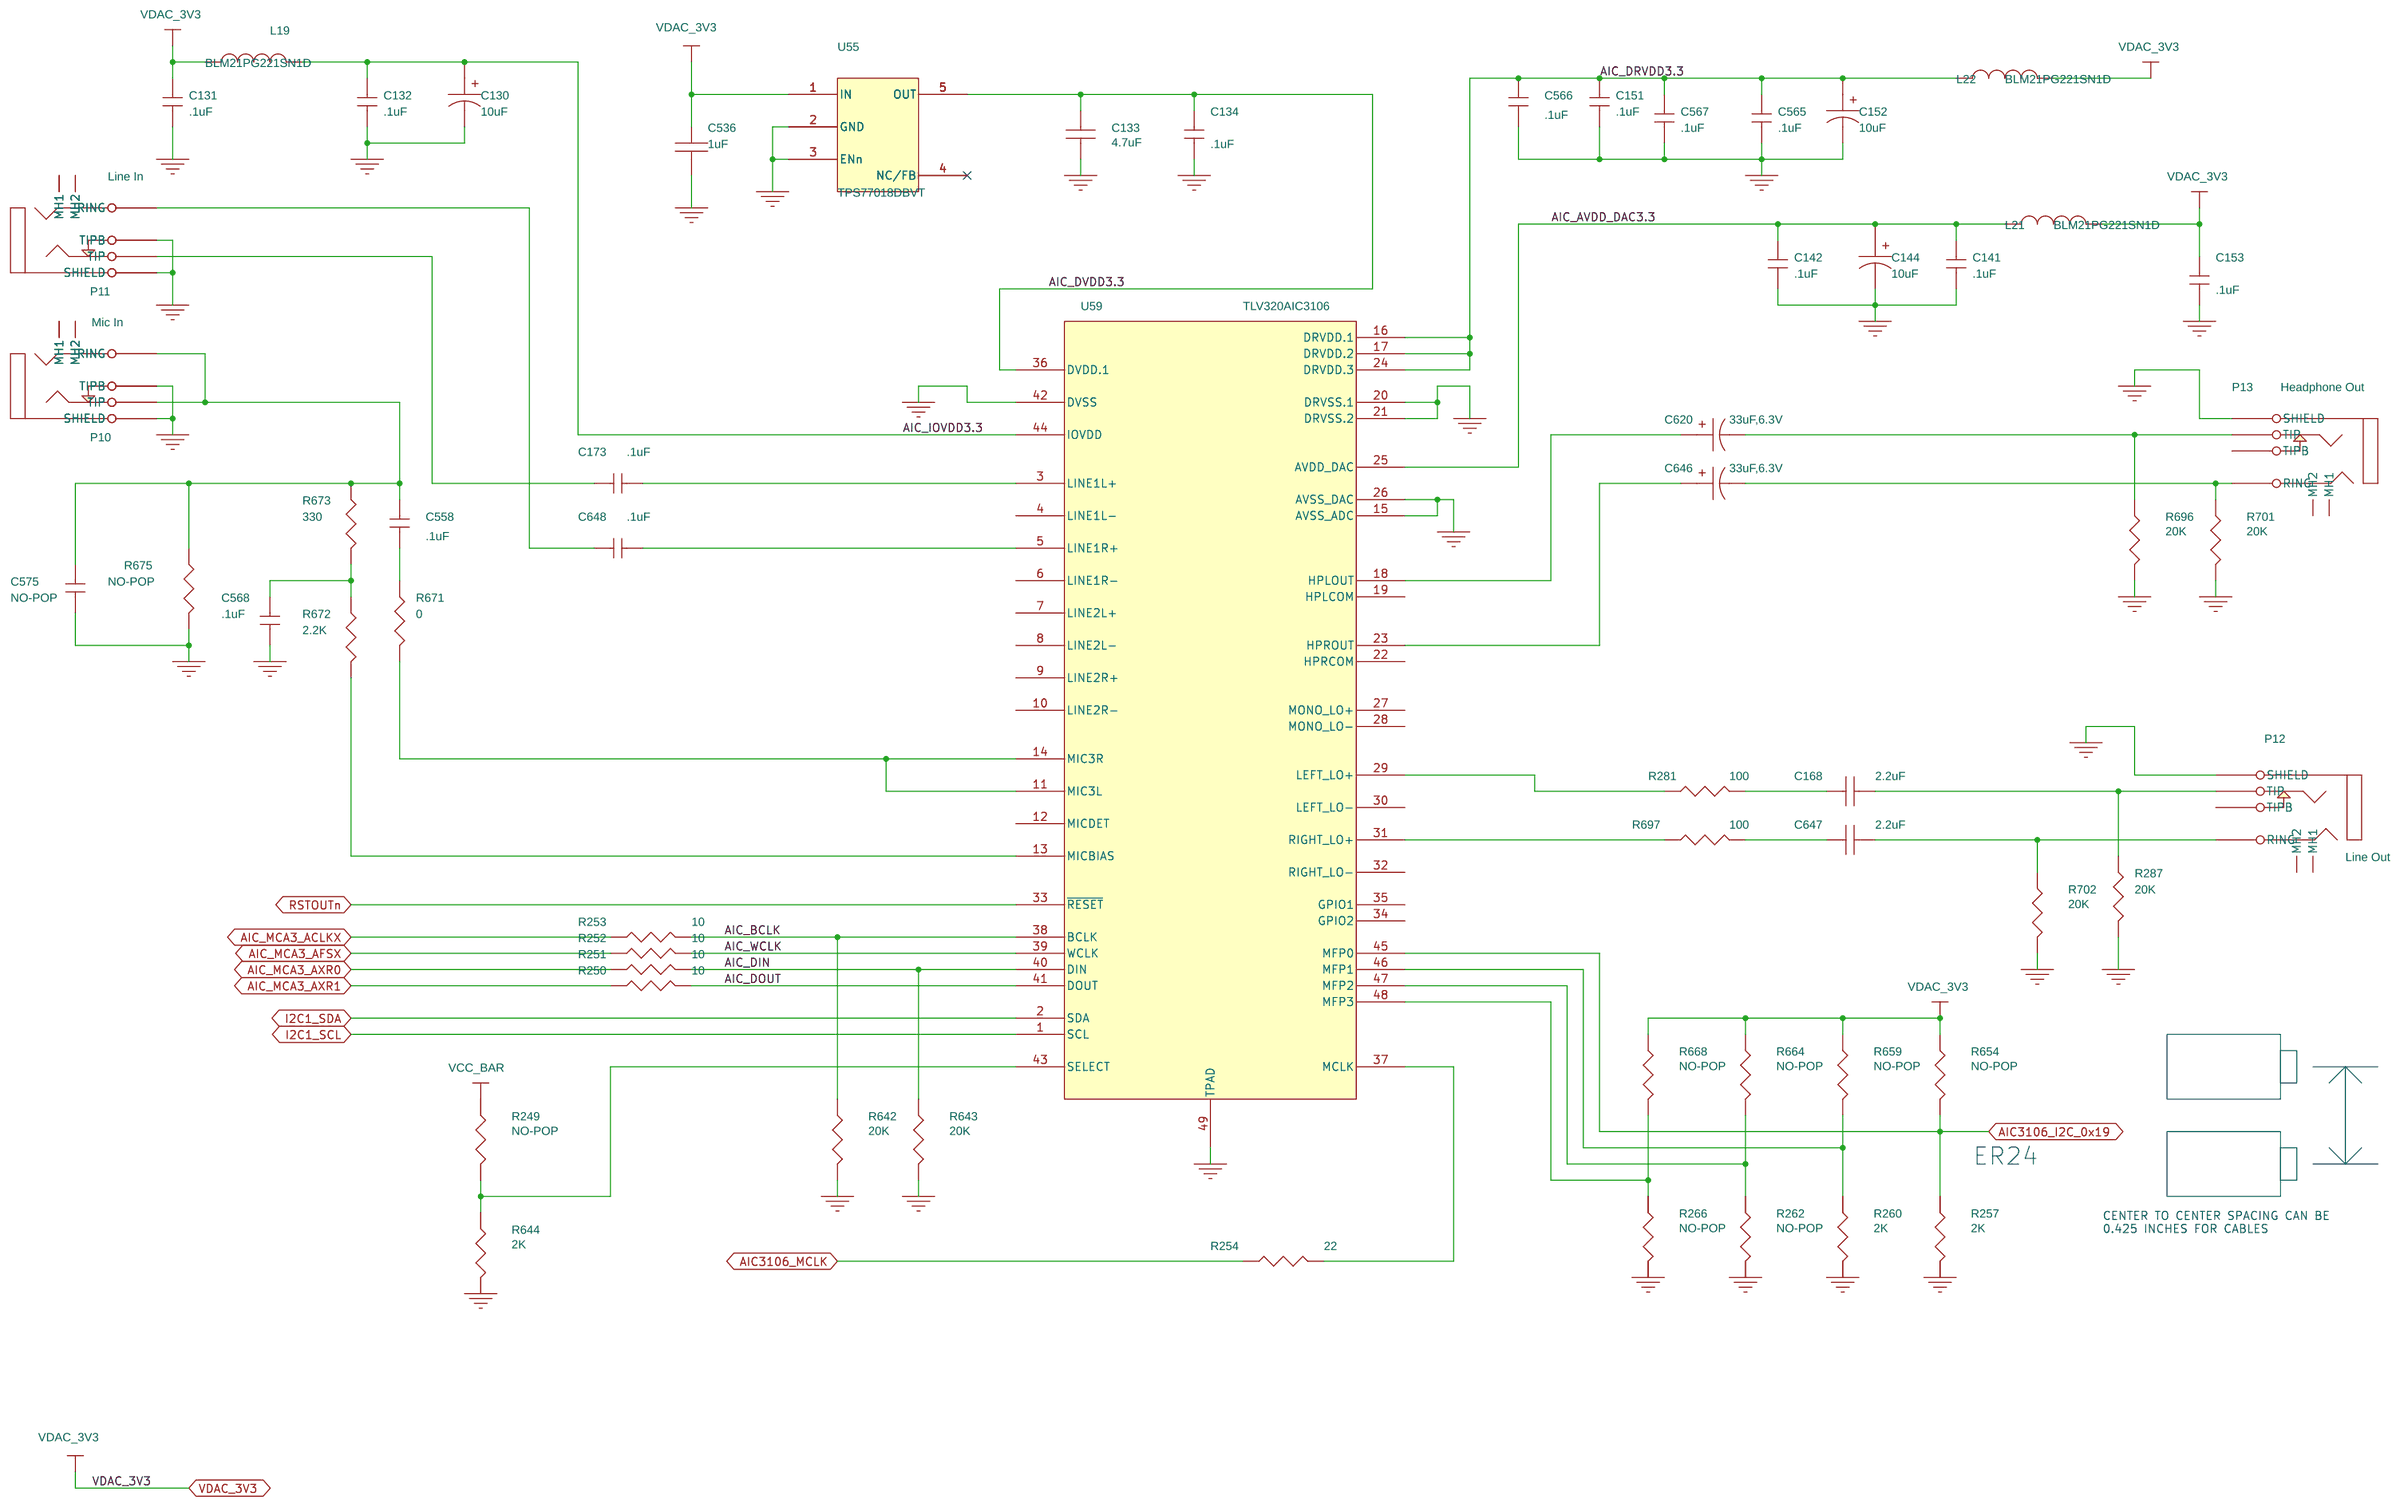
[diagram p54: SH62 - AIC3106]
56 SH63 - ETHERNET PORT0: size B
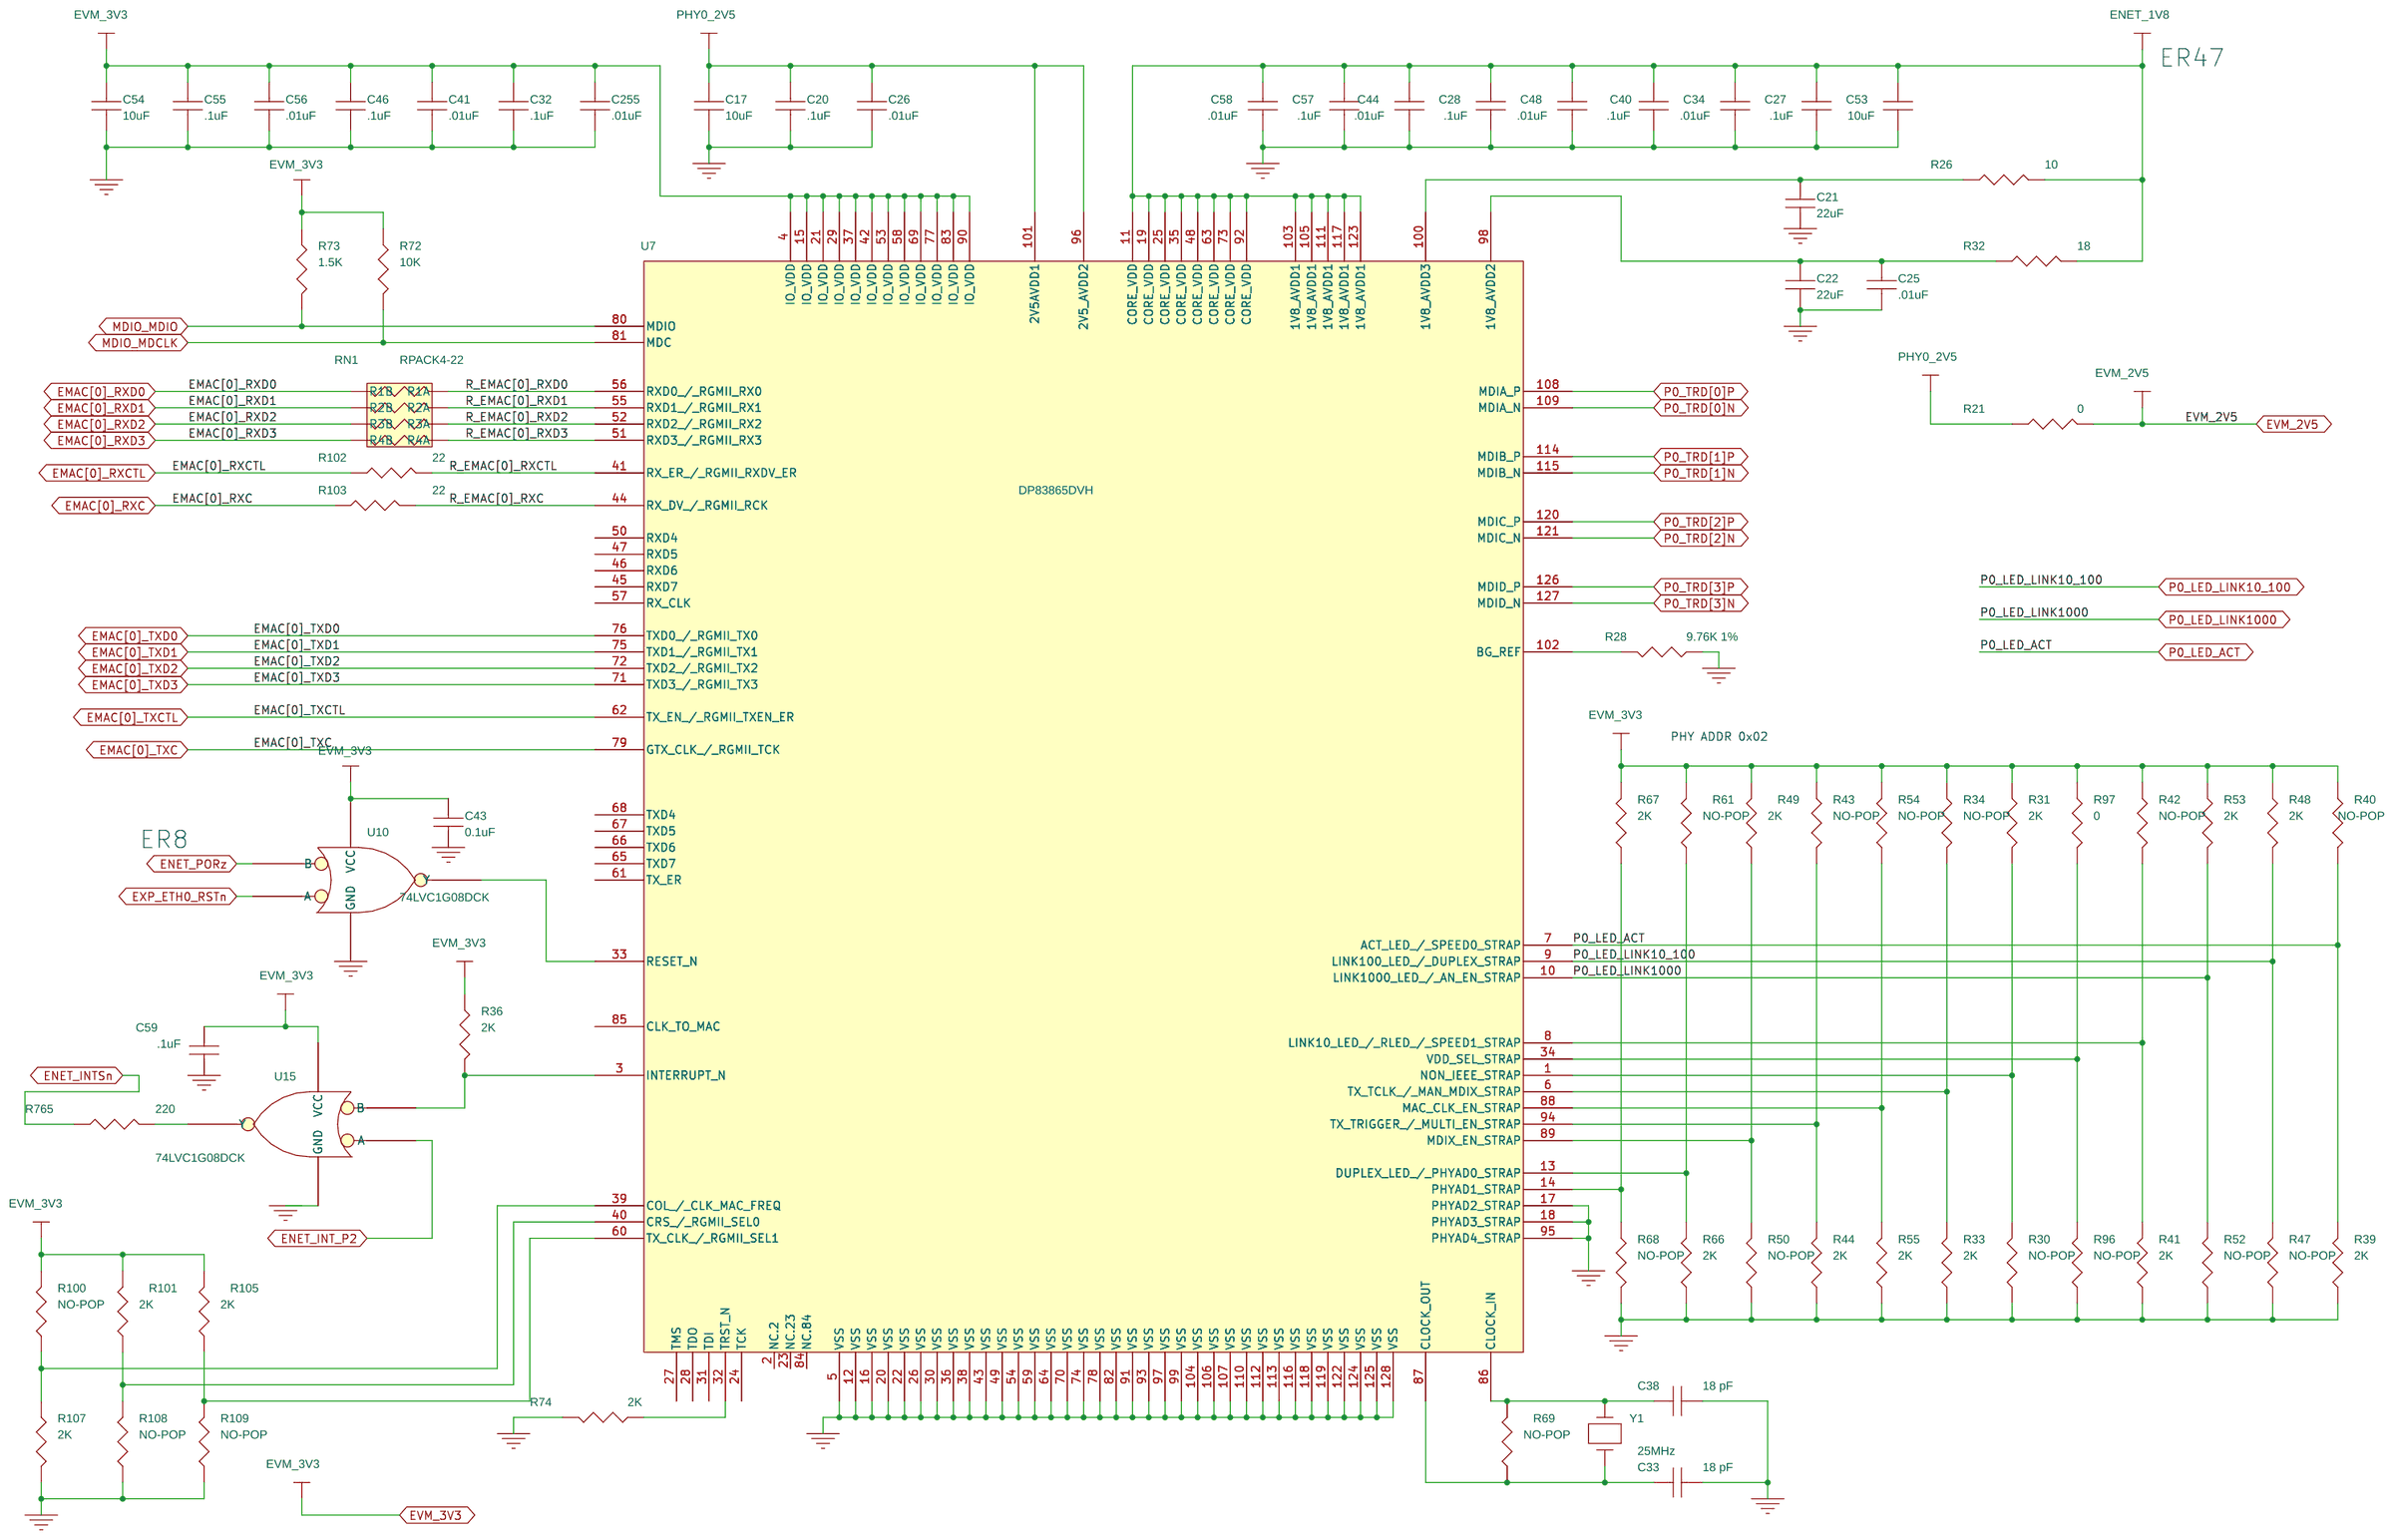
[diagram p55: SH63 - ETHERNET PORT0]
57 SH64 - ETHERNET PORT1: size B
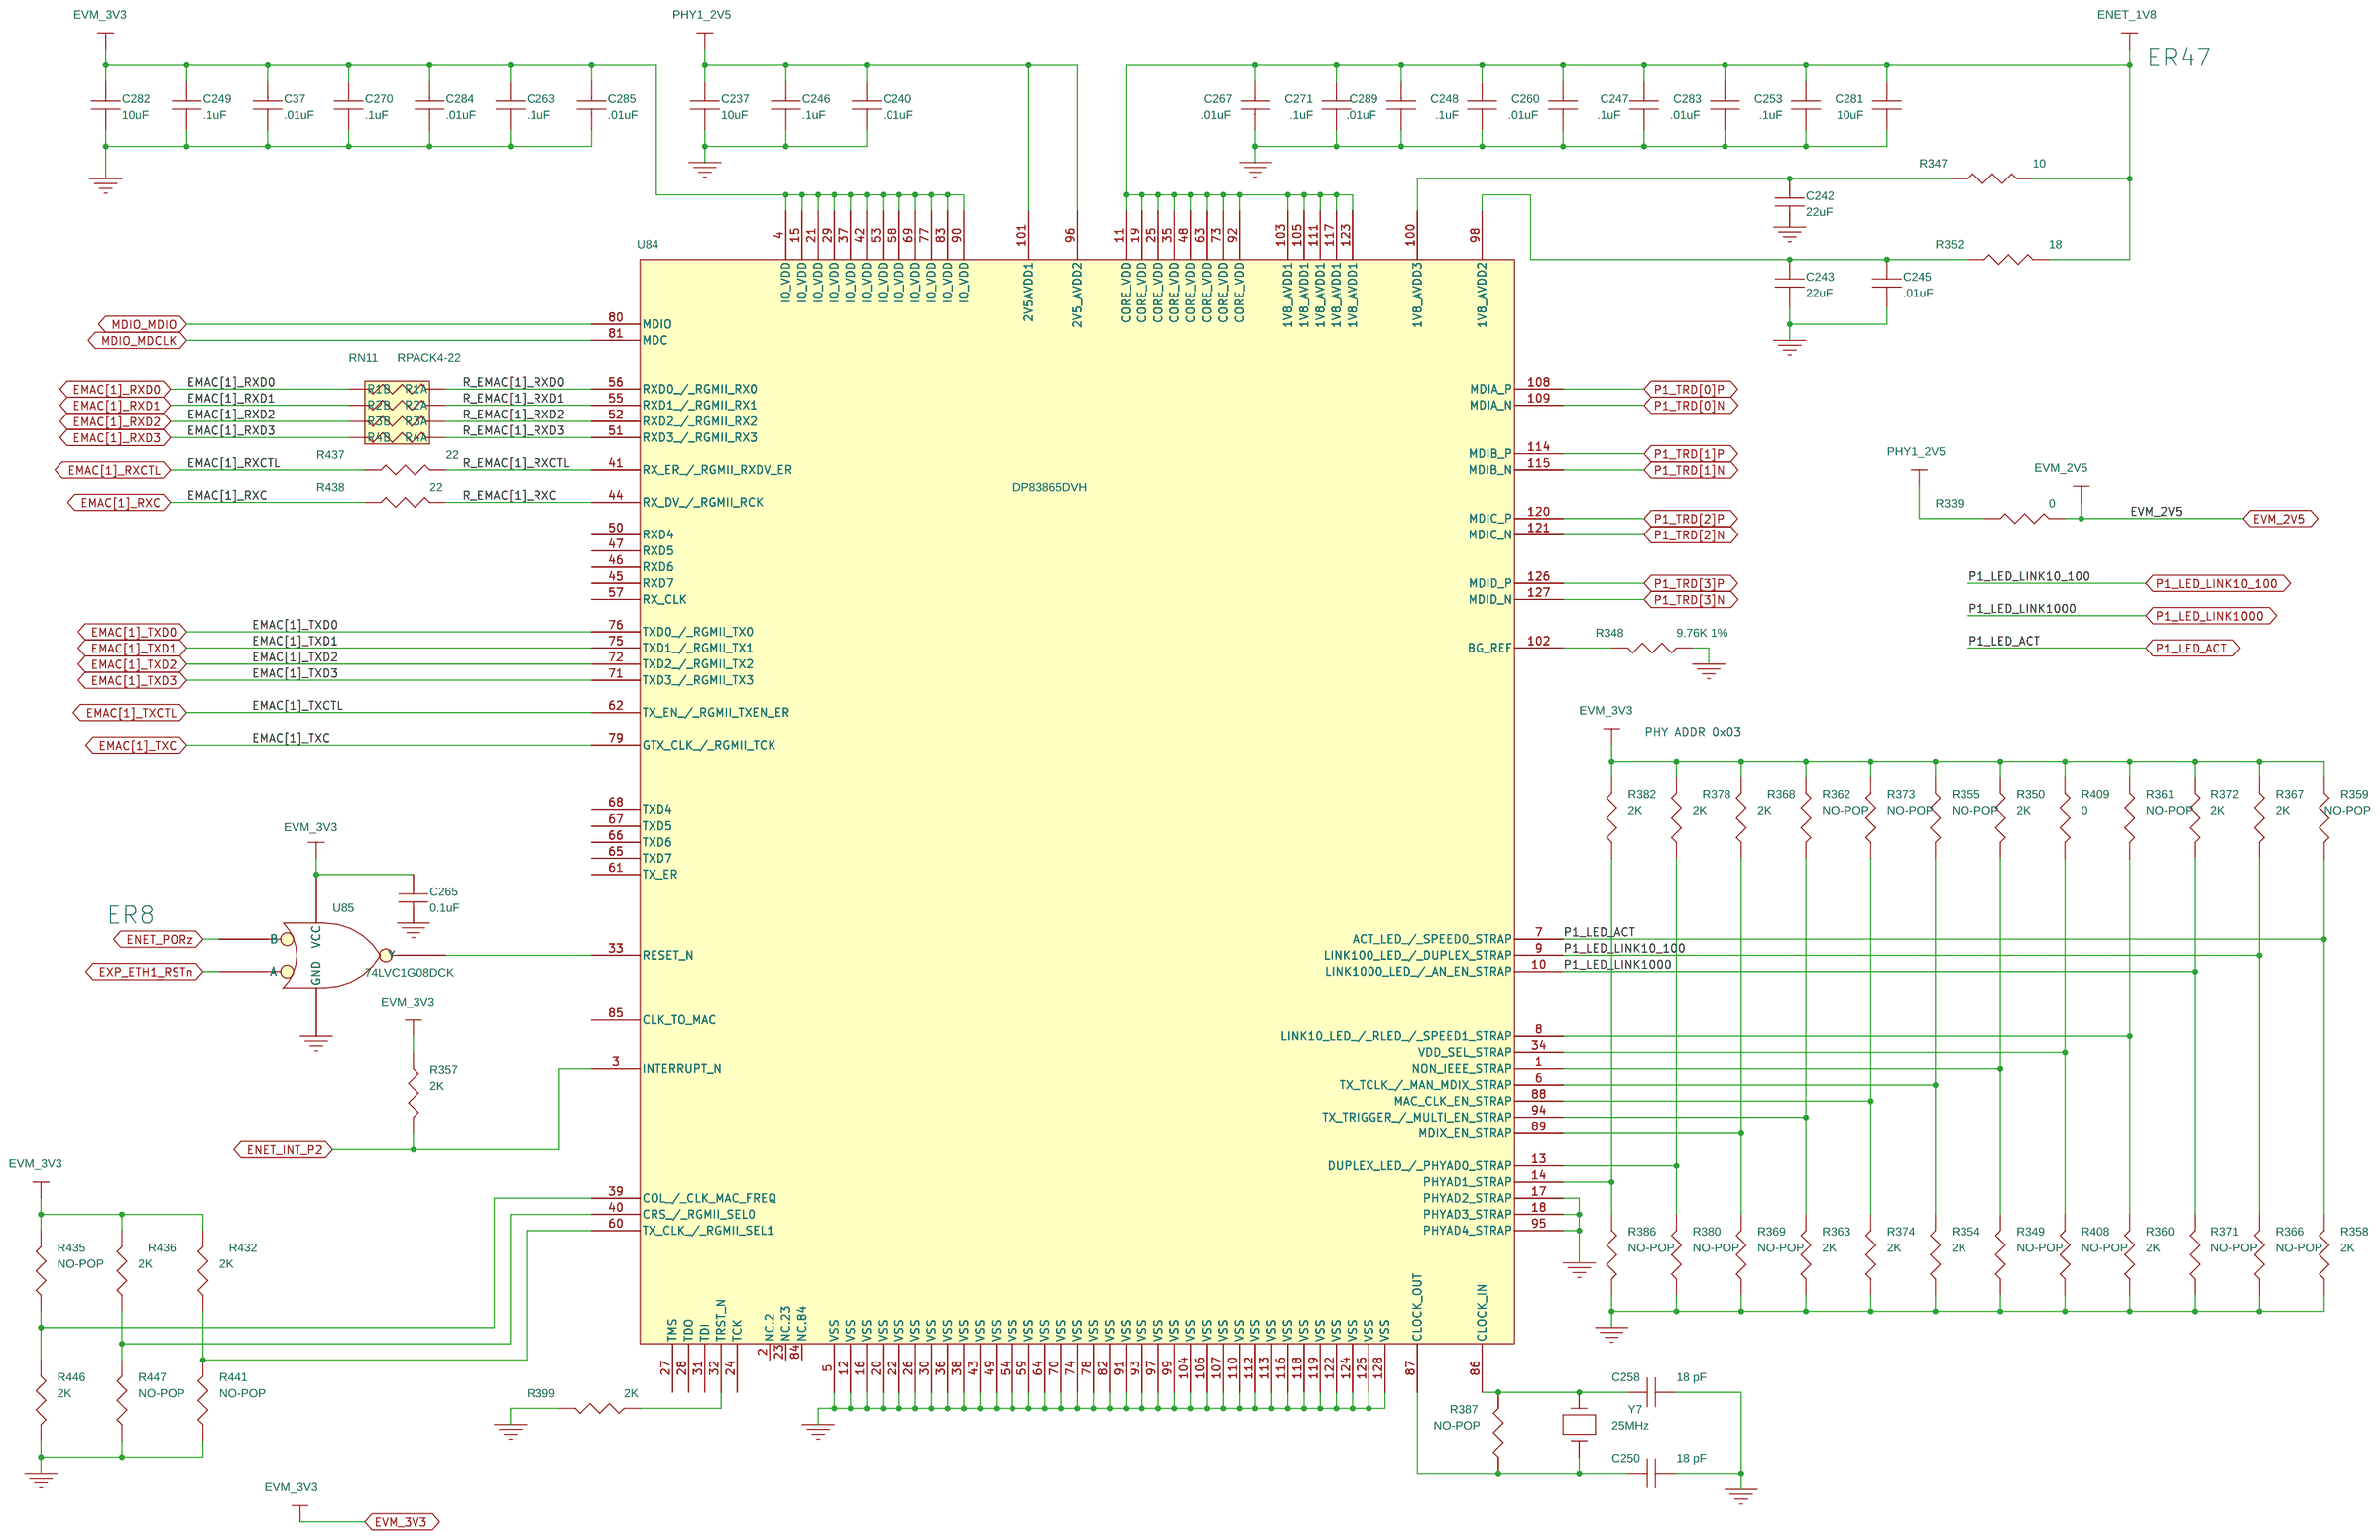
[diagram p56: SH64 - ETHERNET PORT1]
58 SH65 - ETHERNET CONN PORT0 & 1: size B; rev: A
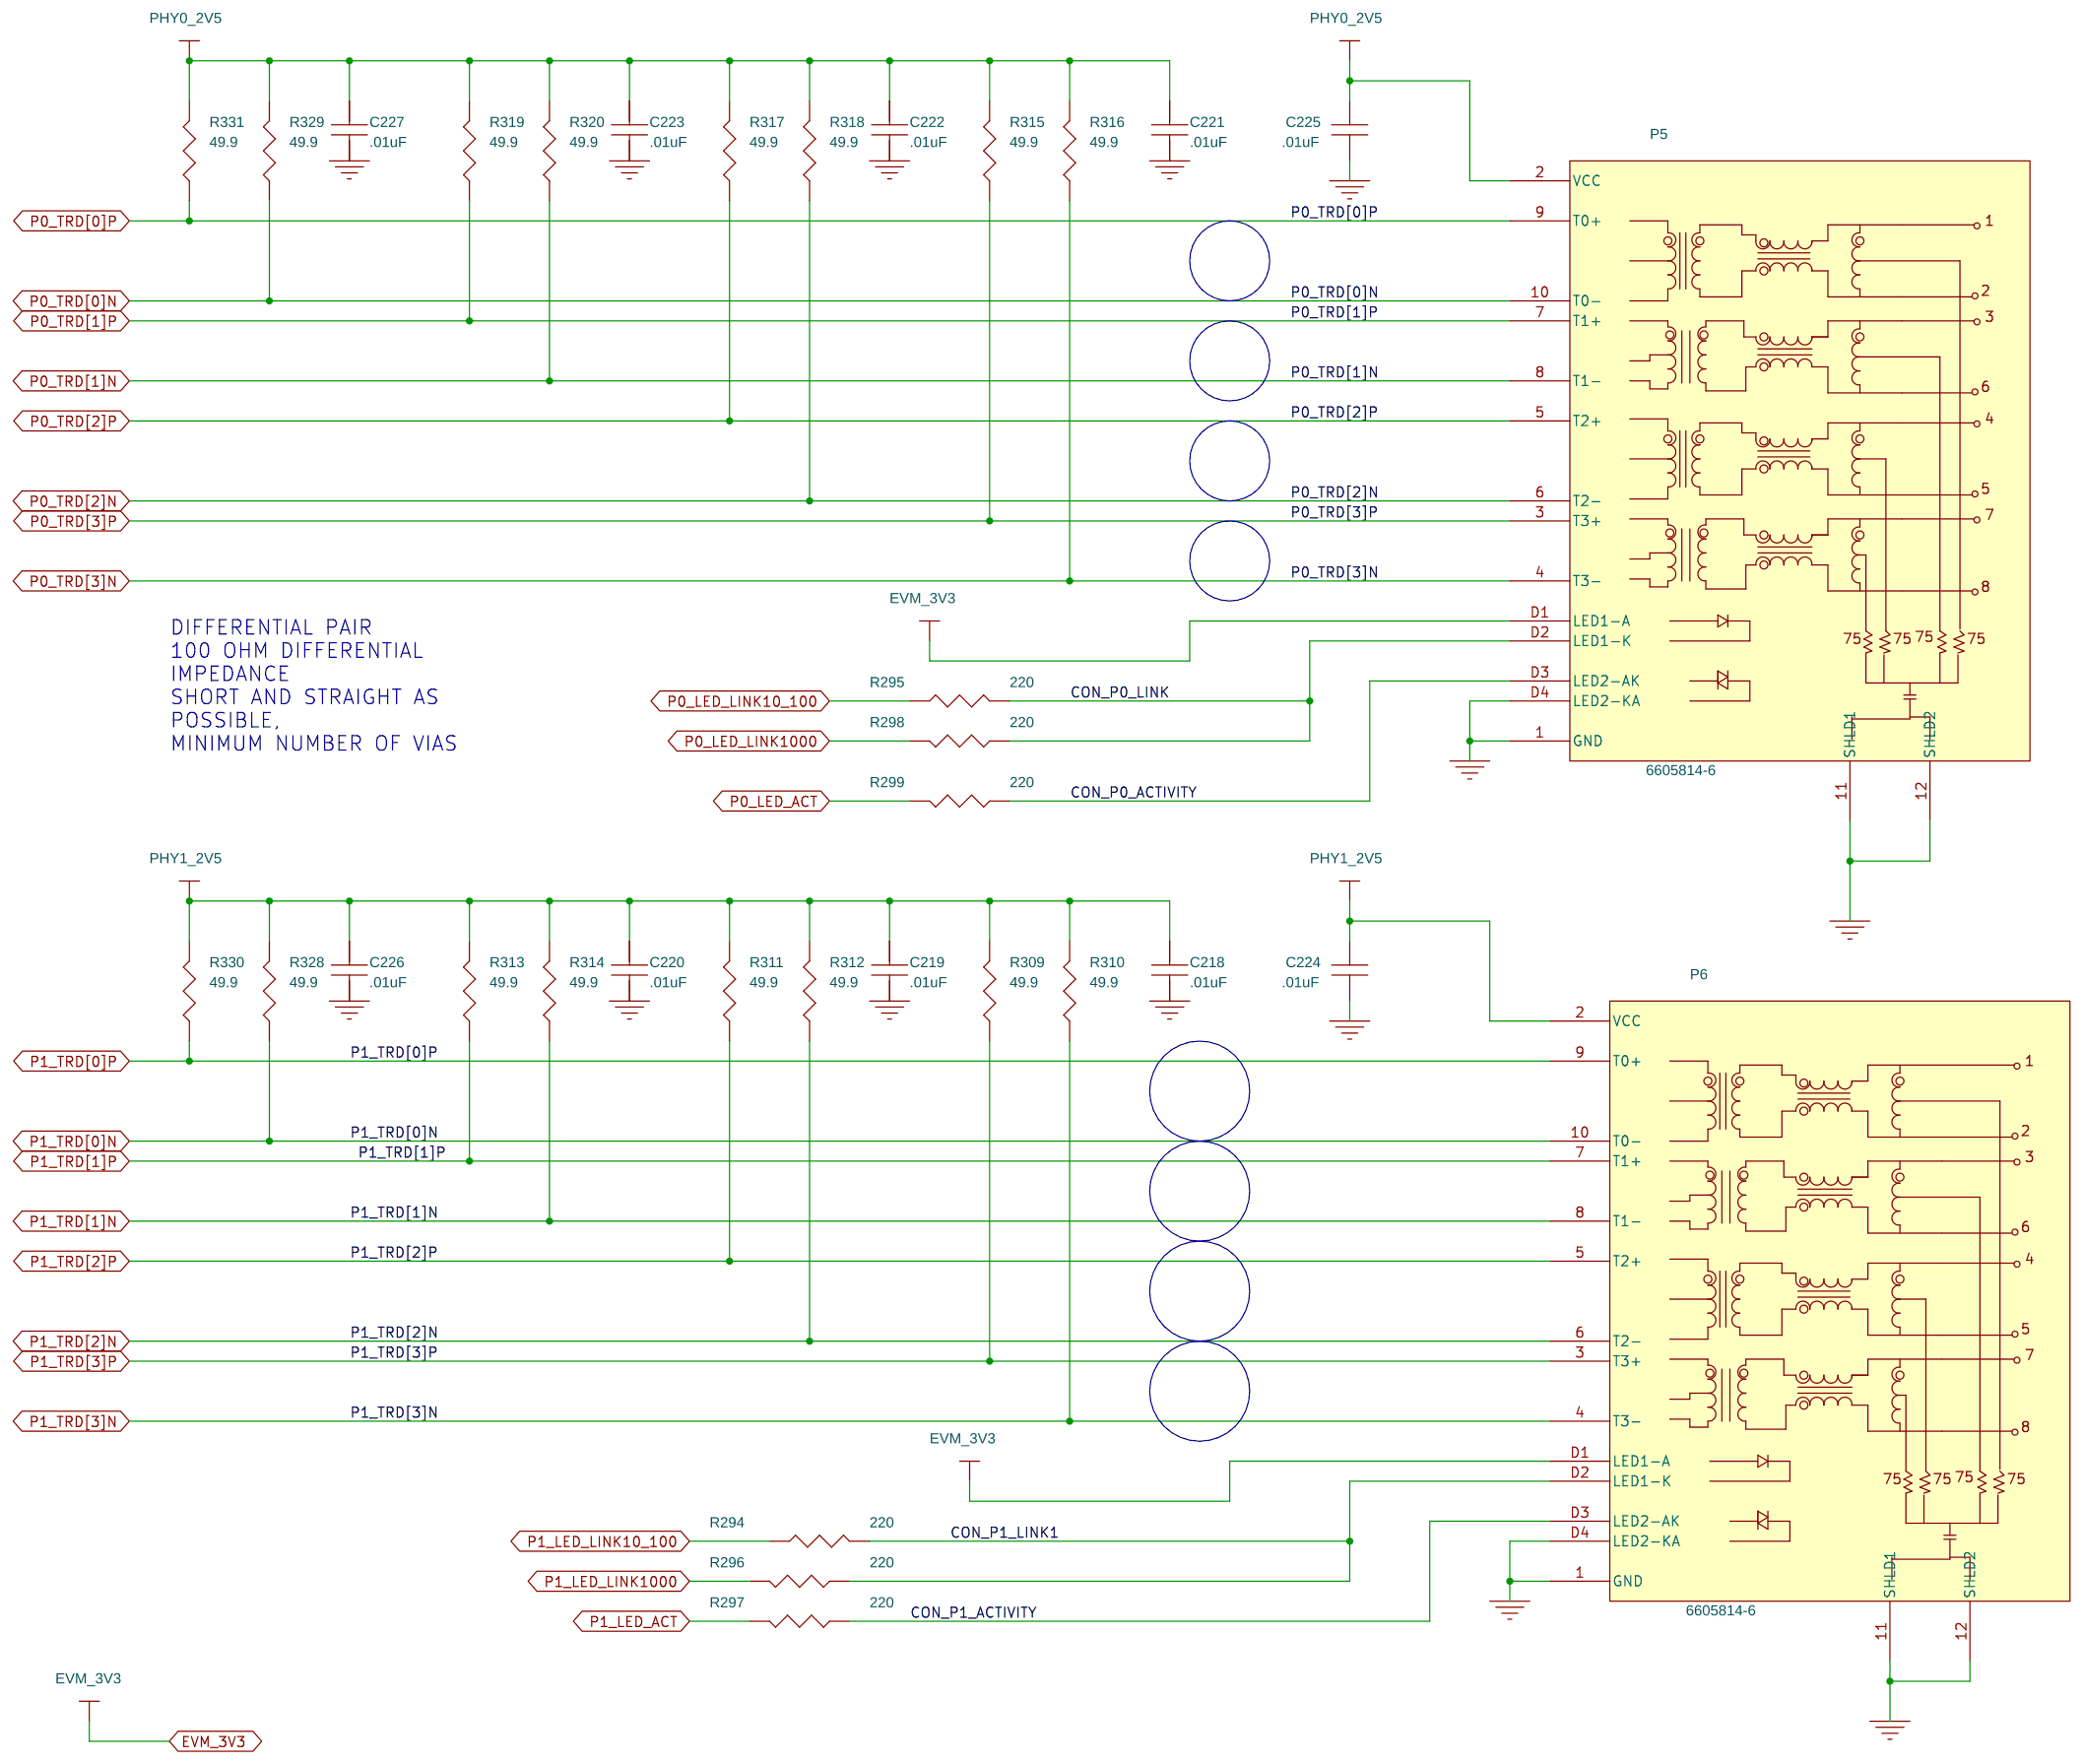
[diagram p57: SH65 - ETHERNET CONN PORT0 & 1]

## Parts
sheet SH54 - DDR3 MEMORY CAPS BANK 2
C158  0.22uF  [c201-6p6spc]
C159  0.22uF  [c201-6p6spc]
C160  0.22uF  [c201-6p6spc]
C161  0.22uF  [c201-6p6spc]
C162  0.22uF  [c201-6p6spc]
C163  0.22uF  [c201-6p6spc]
C169  0.22uF  [c201-6p6spc]
C170  0.22uF  [c201-6p6spc]
C171  0.22uF  [c201-6p6spc]
C172  0.22uF  [c201-6p6spc]
C184  0.22uF  [c201-6p6spc]
C185  0.22uF  [c201-6p6spc]
C189  0.22uF  [c201-6p6spc]
C190  0.22uF  [c201-6p6spc]
C195  0.22uF  [c201-6p6spc]
C196  0.22uF  [c201-6p6spc]
C199  0.22uF  [c201-6p6spc]
C200  0.22uF  [c201-6p6spc]
C581  0.22uF  [c201-6p6spc]
C582  0.22uF  [c201-6p6spc]
C585  0.22uF  [c201-6p6spc]
C586  0.22uF  [c201-6p6spc]
C592  0.22uF  [c201-6p6spc]
C593  0.22uF  [c201-6p6spc]
C595  0.22uF  [c201-6p6spc]
C596  0.22uF  [c201-6p6spc]
C615  0.22uF  [c201-6p6spc]
C616  0.22uF  [c201-6p6spc]
C630  0.22uF  [c201-6p6spc]
C631  0.22uF  [c201-6p6spc]
C636  0.22uF  [c201-6p6spc]
C637  0.22uF  [c201-6p6spc]
C644  0.22uF  [c201-6p6spc]
C645  0.22uF  [c201-6p6spc]
C649  0.22uF  [c201-6p6spc]
C650  0.22uF  [c201-6p6spc]
C664  0.22uF  [c201-6p6spc]
C665  10uF  [c603-35x45]
C666  0.22uF  [c201-6p6spc]
C667  0.22uF  [c201-6p6spc]
C668  0.22uF  [c201-6p6spc]
C669  0.22uF  [c201-6p6spc]
C670  10uF  [c603-35x45]
C671  0.22uF  [c201-6p6spc]
C672  0.22uF  [c201-6p6spc]
C673  10uF  [c603-35x45]
C674  0.22uF  [c201-6p6spc]
C675  0.22uF  [c201-6p6spc]
C676  0.22uF  [c201-6p6spc]
C677  0.22uF  [c201-6p6spc]
C678  10uF  [c603-35x45]
C679  0.22uF  [c201-6p6spc]
sheet SH55 - DDR TERMNATION BANK 2
C166  0.22uF  [c402-25]
C167  0.22uF  [c402-25]
C176  0.22uF  [c402-25]
C181  0.22uF  [c402-25]
C208  0.22uF  [c402-25]
C209  0.22uF  [c402-25]
C601  0.1uF  [c402-25]
C626  0.22uF  [c402-25]
C634  0.22uF  [c402-25]
C642  0.22uF  [c402-25]
C653  0.22uF  [c402-25]
C660  0.22uF  [c402-25]
C661  0.22uF  [c402-25]
R286  49.9/1%  [r402-25]
R685  49.9/1%  [r402-25]
R688  49.9/1%  [r402-25]
R830  49.9-1%  [r402-25]
RN3  R-PACK4-47  [rpak8-10x25-28v]
RN5  R-PACK4-47  [rpak8-10x25-28v]
RN7  R-PACK4-47  [rpak8-10x25-28v]
RN12  R-PACK4-47  [rpak8-10x25-28v]
RN14  R-PACK4-47  [rpak8-10x25-28v]
RN16  R-PACK4-47  [rpak8-10x25-28v]
sheet SH56 - USB VBUS
C79  10uF  [c603-35x45]
C80  .1uF  [c402-25]
C86  10uF  [c603-35x45]
C87  .1uF  [c402-25]
C325  10uF  [c603-35x45]
C340  10uF  [c603-35x45]
L8  BLM21PG221SN1  [l805-35x60]
L12  BLM21PG221SN1  [l805-35x60]
R154  100K  [r402-25]
R179  100K  [r402-25]
R481  10K  [r402-25]
R532  10K  [r402-25]
R770  10K  [r402-25]
R771  10K  [r402-25]
TP27  TestPoint1  [tp1-18rd8]
TP39  TestPoint1  [tp1-18rd8]
U36  TPS2065D  [so8-25x75]
U43  TPS2065D  [so8-25x75]
sheet SH57 - USB CONNECTORS
C217  0.1uF  [c402-25]
C681  0.1uF  [c201-6p6spc]
C682  0.1uF  [c201-6p6spc]
FL1  DLW21SN121HQ2  [EMI-36X15-DLW21-rdpads]
FL2  LW21SN900HQ2  [EMI-36X15-DLW21-rdpads]
FL3  LW21SN900HQ2  [EMI-36X15-DLW21-rdpads]
FL4  DLW21SN121HQ2  [EMI-36X15-DLW21]
P2  AU-Y1009_3-AB-R  [usb-ab-f-10pth-rdpads]
P3  USBMINI_AB  [SAMTEC-MUSB]
R1  10K  [r402-25]
R300  NO-POP  [r402-25]
R301  10K  [r402-25]
R302  10K  [r402-25]
R303  NO-POP  [r402-25]
R306  NO-POP  [r402-25]
R307  10K  [r402-25]
R308  NO-POP  [r402-25]
R323  0  [r402-25]
R324  10K  [r402-25]
R325  0  [r402-25]
R326  10K  [r402-25]
SW1  SW DIP-2  [sw2-30x50-tda]
TP1  TestPoint1  [tp1-18rd8]
TP2  TestPoint1  [tp1-18rd8]
U72  TPD4S014DSQ  [dsq10-son]
U73  TPD4S014DSQ  [dsq10-son]
U124  tpd1e05u06  [dpy-rdpads]
U125  tpd1e05u06  [dpy-rdpads]
U126  tpd1e05u06  [dpy-rdpads]
U127  tpd1e05u06  [dpy-rdpads]
sheet SH58 - FTDI UART
C2  .1uF  [c402-25]
C4  .1uF  [c402-25]
C9  4.7uF  [c603-35x45]
C10  .1uF  [c402-25]
C11  .1uF  [c402-25]
C252  0.1uF  [c402-25]
J1  USBMINI_AB  [SAMTEC-MUSB]
L1  BLM18AG221SN1D  [l603-35x45]
R2  0  [r402-25]
R3  NO-POP  [r402-25]
R4  10K  [r402-25]
R5  NO-POP  [r402-25]
R384  NO-POP  [r201-6p6spc]
RU5  SN74CBTLV3257PW  [tssop16-14x70]
U2  FT232RQ  [qfn32_5x5]
sheet SH59 - COM8 LEVEL TRANSLATOR
C331  0.1uF  [c402-25]
C332  0.1uF  [c402-25]
C335  0.1uF  [c402-25]
C344  0.1uF  [c402-25]
C345  0.1uF  [c402-25]
C351  0.1uF  [c402-25]
C404  0.1uF  [c402-25]
C405  0.1uF  [c402-25]
C411  0.1uF  [c402-25]
C446  0.1uF  [c402-25]
C447  0.1uF  [c402-25]
C448  0.1uF  [c402-25]
C472  0.1uF  [c402-25]
C479  0.1uF  [c402-25]
R157  NO-POP  [r402-25]
R178  10K  [r402-25]
R196  NO-POP  [r402-25]
R200  NO-POP  [r402-25]
R479  NO-POP  [r402-25]
R515  0  [r402-25]
R519  10K  [r402-25]
R520  10K  [r402-25]
R521  10K  [r402-25]
R522  10K  [r402-25]
R523  10K  [r402-25]
R524  10K  [r402-25]
R528  NP  [r402-25]
R536  NO-POP  [R1206-40x70]
R539  NO-POP  [r402-25]
R548  0  [R1206-40x70]
R558  20K  [r402-25]
R559  20K  [r402-25]
R560  20K  [r402-25]
R561  20K  [r402-25]
R562  20K  [r402-25]
R568  NO-POP  [r402-25]
R581  10K  [r402-25]
R584  10K  [r402-25]
R587  NO-POP  [r402-25]
R714  0  [r201-6p6spc]
R715  0  [r201-6p6spc]
U35  SN74AVC8T245RHL  [rhl24-pvqfn-ti]
U41  SN74AVC4T245RGYR  [rgy16-12x34]
U46  SN74AVC8T245RHL  [rhl24-pvqfn-ti]
U48  SN74AVC4T245RGYR_0  [rgy16-12x34]
U100  TXS0108EPW  [pw20-14x70]
U104  SN74LVC1T45  [DCK-17X60-6]
sheet SH60 - COM8 CONNECTOR
J2  HEADER 3  [JUMP1X3-6040]
J16  HEADER 3  [JUMP1X3-6040]
P9  MEC6-150-02-S-D-RA1  [mec6-150-ra1]
R222  0  [r402-25]
R593  2K  [r402-25]
R597  2K  [r402-25]
R600  0  [r402-25]
R603  4.7k  [r402-25]
TP22  TESTPOINT  [tp-20RD10]
TP23  TESTPOINT  [tp-20RD10]
TP44  TESTPOINT  [tp-20RD10]
TP45  TESTPOINT  [tp-20RD10]
TP46  TESTPOINT  [tp-20RD10]
TP47  TESTPOINT  [tp-20RD10]
TP48  TESTPOINT  [tp-20RD10]
TP49  TESTPOINT  [tp-20RD10]
U50  PCA9306/PCA9306-Q1  [dcu8-10x50]
sheet SH61 - COM8 POWER
C503  10uF  [c603-35x45]
C515  5.6pF  [c402-25]
C532  0.001uF  [c402-25]
C546  2.2uF  [c603-35x45]
R241  4.99K  [r603-35x45]
R244  17.4K  [r603-35x45]
U56  TPS74801  [drc10-11x33]
sheet SH62 - AIC3106
C130  10uF  [c1206-40x70-POL]
C131  .1uF  [c402-25]
C132  .1uF  [c402-25]
C133  4.7uF  [c603-35x45]
C134  .1uF  [c402-25]
C141  .1uF  [c402-25]
C142  .1uF  [c402-25]
C144  10uF  [c1206-40x70-POL]
C151  .1uF  [c402-25]
C152  10uF  [c1206-40x70-POL]
C153  .1uF  [c402-25]
C168  2.2uF  [c603-35x45]
C173  .1uF  [c402-25]
C536  1uF  [c402-25]
C558  .1uF  [c402-25]
C565  .1uF  [c402-25]
C566  .1uF  [c402-25]
C567  .1uF  [c402-25]
C568  .1uF  [c402-25]
C575  NO-POP  [c402-25]
C620  33uF,6.3V  [c1206-40x70p]
C646  33uF,6.3V  [c1206-40x70p]
C647  2.2uF  [c603-35x45]
C648  .1uF  [c402-25]
L19  BLM21PG221SN1D  [l805-35x60]
L21  BLM21PG221SN1D  [l805-35x60]
L22  BLM21PG221SN1D  [l805-35x60]
P10  Mic In  [st_3500]
P11  Line In  [st_3500]
P12  Line Out  [st_3500]
P13  Headphone Out  [st_3500]
R249  NO-POP  [r402-25]
R250  10  [r402-25]
R251  10  [r402-25]
R252  10  [r402-25]
R253  10  [r402-25]
R254  22  [r402-25]
R257  2K  [r402-25]
R260  2K  [r402-25]
R262  NO-POP  [r402-25]
R266  NO-POP  [r402-25]
R281  100  [r402-25]
R287  20K  [r402-25]
R642  20K  [r402-25]
R643  20K  [r402-25]
R644  2K  [r402-25]
R654  NO-POP  [r402-25]
R659  NO-POP  [r402-25]
R664  NO-POP  [r402-25]
R668  NO-POP  [r402-25]
R671  0  [r402-25]
R672  2.2K  [r402-25]
R673  330  [r402-25]
R675  NO-POP  [r402-25]
R696  20K  [r402-25]
R697  100  [r402-25]
R701  20K  [r402-25]
R702  20K  [r402-25]
U55  TPS77018DBVT  [dbv5-27x39]
U59  TLV320AIC3106  [rgz48-11x34]
sheet SH63 - ETHERNET PORT0
C17  10uF  [c603-35x45]
C20  .1uF  [c402-25]
C21  22uF  [c603-35x45]
C22  22uF  [c603-35x45]
C25  .01uF  [c402-25]
C26  .01uF  [c402-25]
C27  .1uF  [c402-25]
C28  .1uF  [c402-25]
C32  .1uF  [c402-25]
C33  18 pF  [c603-35x45]
C34  .01uF  [c402-25]
C38  18 pF  [c603-35x45]
C40  .1uF  [c402-25]
C41  .01uF  [c402-25]
C43  0.1uF  [c402-25]
C44  .01uF  [c402-25]
C46  .1uF  [c402-25]
C48  .01uF  [c402-25]
C53  10uF  [c603-35x45]
C54  10uF  [c603-35x45]
C55  .1uF  [c402-25]
C56  .01uF  [c402-25]
C57  .1uF  [c402-25]
C58  .01uF  [c402-25]
C59  .1uF  [c402-25]
C255  .01uF  [c402-25]
R21  0  [r1206-40X70]
R26  10  [r805-35x60]
R28  9.76K 1%  [r402-25]
R30  NO-POP  [r402-25]
R31  2K  [r402-25]
R32  18  [r805-35x60]
R33  2K  [r402-25]
R34  NO-POP  [r402-25]
R36  2K  [r402-25]
R39  2K  [r402-25]
R40  NO-POP  [r402-25]
R41  2K  [r402-25]
R42  NO-POP  [r402-25]
R43  NO-POP  [r402-25]
R44  2K  [r402-25]
R47  NO-POP  [r402-25]
R48  2K  [r402-25]
R49  2K  [r402-25]
R50  NO-POP  [r402-25]
R52  NO-POP  [r402-25]
R53  2K  [r402-25]
R54  NO-POP  [r402-25]
R55  2K  [r402-25]
R61  NO-POP  [r402-25]
R66  2K  [r402-25]
R67  2K  [r402-25]
R68  NO-POP  [r402-25]
R69  NO-POP  [r402-25]
R72  10K  [r402-25]
R73  1.5K  [r402-25]
R74  2K  [r402-25]
R96  NO-POP  [r402-25]
R97  0  [r402-25]
R100  NO-POP  [r402-25]
R101  2K  [r402-25]
R102  22  [r402-25]
R103  22  [r402-25]
R105  2K  [r402-25]
R107  2K  [r402-25]
R108  NO-POP  [r402-25]
R109  NO-POP  [r402-25]
R765  220  [r402-25]
RN1  RPACK4-22  [rpak8-10x25-28v]
U7  DP83865DVH  [PQFP128REC-12X70]
U10  74LVC1G08DCK  [dck-5]
U15  74LVC1G08DCK  [dck-5]
Y1  25MHz  [xtal2-75x94]
sheet SH64 - ETHERNET PORT1
C37  .01uF  [c402-25]
C237  10uF  [c603-35x45]
C240  .01uF  [c402-25]
C242  22uF  [c603-35x45]
C243  22uF  [c603-35x45]
C245  .01uF  [c402-25]
C246  .1uF  [c402-25]
C247  .1uF  [c402-25]
C248  .1uF  [c402-25]
C249  .1uF  [c402-25]
C250  18 pF  [c603-35x45]
C253  .1uF  [c402-25]
C258  18 pF  [c603-35x45]
C260  .01uF  [c402-25]
C263  .1uF  [c402-25]
C265  0.1uF  [c402-25]
C267  .01uF  [c402-25]
C270  .1uF  [c402-25]
C271  .1uF  [c402-25]
C281  10uF  [c603-35x45]
C282  10uF  [c603-35x45]
C283  .01uF  [c402-25]
C284  .01uF  [c402-25]
C285  .01uF  [c402-25]
C289  .01uF  [c402-25]
R339  0  [r1206-40X70]
R347  10  [r805-35x60]
R348  9.76K 1%  [r402-25]
R349  NO-POP  [r402-25]
R350  2K  [r402-25]
R352  18  [r805-35x60]
R354  2K  [r402-25]
R355  NO-POP  [r402-25]
R357  2K  [r402-25]
R358  2K  [r402-25]
R359  NO-POP  [r402-25]
R360  2K  [r402-25]
R361  NO-POP  [r402-25]
R362  NO-POP  [r402-25]
R363  2K  [r402-25]
R366  NO-POP  [r402-25]
R367  2K  [r402-25]
R368  2K  [r402-25]
R369  NO-POP  [r402-25]
R371  NO-POP  [r402-25]
R372  2K  [r402-25]
R373  NO-POP  [r402-25]
R374  2K  [r402-25]
R378  2K  [r402-25]
R380  NO-POP  [r402-25]
R382  2K  [r402-25]
R386  NO-POP  [r402-25]
R387  NO-POP  [r402-25]
R399  2K  [r402-25]
R408  NO-POP  [r402-25]
R409  0  [r402-25]
R432  2K  [r402-25]
R435  NO-POP  [r402-25]
R436  2K  [r402-25]
R437  22  [r402-25]
R438  22  [r402-25]
R441  NO-POP  [r402-25]
R446  2K  [r402-25]
R447  NO-POP  [r402-25]
RN11  RPACK4-22  [rpak8-10x25-28v]
U84  DP83865DVH  [PQFP128REC-12X70]
U85  74LVC1G08DCK  [dck-5]
Y7  25MHz  [xtal2-75x94]
sheet SH65 - ETHERNET CONN PORT0 & 1
C218  .01uF  [c402-25]
C219  .01uF  [c402-25]
C220  .01uF  [c402-25]
C221  .01uF  [c402-25]
C222  .01uF  [c402-25]
C223  .01uF  [c402-25]
C224  .01uF  [c402-25]
C225  .01uF  [c402-25]
C226  .01uF  [c402-25]
C227  .01uF  [c402-25]
P5  6605814-6  [amp-6605814]
P6  6605814-6  [amp-6605814]
R294  220  [r402-25]
R295  220  [r402-25]
R296  220  [r402-25]
R297  220  [r402-25]
R298  220  [r402-25]
R299  220  [r402-25]
R309  49.9  [r402-25]
R310  49.9  [r402-25]
R311  49.9  [r402-25]
R312  49.9  [r402-25]
R313  49.9  [r402-25]
R314  49.9  [r402-25]
R315  49.9  [r402-25]
R316  49.9  [r402-25]
R317  49.9  [r402-25]
R318  49.9  [r402-25]
R319  49.9  [r402-25]
R320  49.9  [r402-25]
R328  49.9  [r402-25]
R329  49.9  [r402-25]
R330  49.9  [r402-25]
R331  49.9  [r402-25]

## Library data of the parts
C158 = CAP: Part #: 103214-1220R
C159-C163 C169-C172 C184 C185 C189 C190 C195 C196 C199 C200 C581 C582 C585 C586 C592 C593 C595 C596 C615 C616 C630 C631 C636 C637 C644 C645 C649 C650 C664 C666-C669 C671 C672 C674-C677 C679 = CAP_NP_0: Part #: 103214-1220R
C17 C53 C54 C79 C86 C237 C281 C282 C325 C340 C665 C670 C673 C678 = CAP: Part #: 102963-0101R
C166 C167 C176 C181 C208 C209 C626 C634 C642 C653 C660 C661 = CAP_NP_0: Part #: 101587-1220R
C601 = SC10N16V2KX_0: Part #: 101587-1100R
R286 R309-R320 R328-R331 R830 = R: Part #: 102145-4990R
R685 R688 = 1KR2F_0: Part #: 102145-4990R
RN3 RN5 RN7 RN12 RN14 RN16 = R-Pak4_0: Part #: 101327-4700R
C2 C4 C10 C11 C80 C87 C131 C132 C134 C141 C142 C151 C153 C173 C252 C405 C411 C558 C565-C568 C648 = CAP_NP: Part #: 101587-1100R
L8 L12 = INDUCTOR_3: Part #: 101228-2201R
R154 R179 = R: Part #: 101370-1004R
R1 R72 R178 R301 R302 R307 R326 R481 R519-R524 R532 R581 R584 R770 R771 = R: Part #: 101370-1003R
TP1 TP2 TP27 TP39 = TestPoint1_0: Part #: TP-18RD8-NO-POP
U36 U43 = tps2061_1: Part #: 102810-0001R
C217 = Cap_100nF_Cermc_16V_10%_603_4: Part #: 101587-1100R
C681 C682 = CAP_NP_2: Part #: 103241-1100R
FL1 FL4 = DLW21SN121HQ2: Part #: 104184-1201R
FL2 FL3 = DLW21SN121HQ2: Part #: 104184-9000R
P2 = AU-Y1009_3-AB-R: Part #: 104383-0001R
J1 P3 = USBMINI_B_0: Part #: 101956-0001R
R30 R34 R40 R42 R43 R47 R50 R52 R54 R61 R68 R69 R96 R100 R108 R109 R157 R196 R200 R300 R303 R306 R308 R349 R355 R359 R361 R362 R366 R369 R371 R373 R380 R386 R387 R408 R435 R441 R447 R479 R528 R539 R568 R587 = R: Part #: R0402-NOPOP
R323 = RESISTOR_0: Part #: 101370-0001R
R324 = RESISTOR_0: Part #: 101370-1003R
R97 R222 R325 R409 R515 R600 = R: Part #: 101370-0001R
SW1 = SW_DIP-2: Part #: 101184-0002R
U72 U73 = TPD4S014DSQ: Part #: 104147-0001R
U124-U127 = tpd1e05u06: Part #: 104410-0001R
C9 C133 = CAP_NP_2: Part #: 102590-0470R
L1 = FERRITE_CHIP_0: Part #: 101858-2201R
R2 R671 = R_0: Part #: 101370-0001R
R3 R5 R249 R262 R266 R654 R659 R664 R668 R675 = R_0: Part #: R0402-NOPOP
R4 = R_0: Part #: 101370-1003R
R384 = R: Part #: R0201-NOPOP
RU5 = SN74CBT3257PW: Part #: 101670-0001R
U2 = FT232RQ_7: Part #: 103625-0001R
C20 C27 C28 C32 C40 C43 C46 C55 C57 C246-C249 C253 C263 C265 C270 C271 C331 C332 C335 C344 C345 C351 C404 C446-C448 C472 C479 = CAP: Part #: 101587-1100R
R536 = R: Part #: R1206-NOPOP
R21 R339 R548 = R: Part #: 100155-0001R
R558-R562 = R: Part #: 101370-2003R
R714 R715 = R: Part #: 103158-0001R
U35 U46 = SN74AVC8T245_1: Part #: 102708-0001R
U41 U48 = SN74AVC4T245RGYR_0: Part #: 102649-0245R
U100 = TXB0108PWR_0: Part #: 103666-0001R
U104 = TMP_1: Part #: 102156-0001R
J2 J16 = HEADER_3: Part #: 100115-0003R
P9 = HEADER_50x2: Part #: 103626-0050R
R593 R597 = RESISTOR_0: Part #: 101370-2002R
R603 = RESISTOR_0: Part #: 101370-4702R
TP22 TP23 TP44-TP49 = TESTPOINT: Part #: TP-20RD10-NO-POP
U50 = PCA9306: Part #: 103282-0001R
C503 = CAP_NP: Part #: 102963-0101R
C515 = Cap_100nF_Cermc_16V_10%_603_3: Part #: 101782-1565R
C532 = CAP_NP: Part #: 102058-1102R
C546 = CAP_NP: Part #: 101007-0220R
R241 = R_3: Part #: 100642-4992R
R244 = R_3: Part #: 100642-1743R
U56 = U-TPS78601_AJUST_-_1_3.5A_LDO: Part #: 104335-0001R
C130 C144 C152 = CAPACITOR_POL_0: Part #: 101003-0101R
C168 C647 = CAP: Part #: 102965-0220R
C536 = C_0: Part #: 102962-0100R
C575 = CAP_NP: Part #: C0402-NOPOP
C620 C646 = CAPACITOR_POL_0: Part #: 101953-0331R
L19 L21 L22 = INDUCTOR: Part #: 101228-2201R
P10-P13 = Kycon_ST-3500_0: Part #: 101012-0001R
R250-R253 = R_0: Part #: 101370-1000R
R254 = RESISTOR: Part #: 101370-2200R
R257 R260 R644 = R_0: Part #: 101370-2002R
R281 R697 = R: Part #: 101370-1001R
R287 R642 R643 R696 R701 R702 = R_0: Part #: 101370-2003R
R672 = R_0: Part #: 101370-2202R
R673 = R_0: Part #: 101370-3301R
U55 = TPS76901_1: Part #: 101320-0018R
U59 = TLV320AIC3106_0: Part #: 102800-0001R
C21 C22 C242 C243 = CAP: Part #: 103911-0221R
C25 C26 C34 C37 C41 C44 C48 C56 C58 C218-C227 C240 C245 C255 C260 C267 C283-C285 C289 = CAP: Part #: 101587-1101R
C33 C38 C250 C258 = CAP_NP_3: Part #: 101103-1184R
C59 = CAP_NP_2: Part #: 101587-1100R
R26 R347 = R: Part #: 100552-1000R
R28 R348 = R: Part #: 102145-9762R
R31 R33 R36 R39 R41 R44 R48 R49 R53 R55 R66 R67 R74 R101 R105 R107 R350 R354 R357 R358 R360 R363 R367 R368 R372 R374 R378 R382 R399 R432 R436 R446 = R: Part #: 101370-2002R
R32 R352 = R: Part #: 100552-1800R
R73 = R: Part #: 101370-1502R
R102 R103 R437 R438 = R: Part #: 101370-2200R
R294 R295 R765 = R: Part #: 101370-2201R
RN1 RN11 = R-Pak4_0: Part #: 101327-2200R
U7 U84 = DP83865DVH_0
U10 U15 U85 = 1G08: Part #: 101057-0008R
Y1 Y7 = CRYSTAL_0_v2: Part #: 101590-0250R
P5 P6 = 66058414_1: Part #: 103166-0001R
R296-R299 = RES_0: Part #: 101370-2201R

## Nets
1V8_I2C1_SCL: P9.31 R597.2 U50.3(SCL1) ; also on sheet 63
1V8_I2C1_SDA: P9.33 R593.2 U50.4(SDA1) ; also on sheet 63
GND: C2.2 C4.2 C9.2 C10.2 C11.2 C17.2 C20.2 C21.2 C22.2 C25.2 C26.2 C27.2 C28.2 C32.2 C33.2 C34.2 C37.2 C38.2 C40.2 C41.2 C43.2 C44.2 C46.2 C48.2 C53.2 C54.2 C55.2 C56.2 C57.2 C58.2 C59.2 C79.2 C80.2 C86.2 C87.2 C130.2 C131.2 C132.2 C133.2 C134.2 C141.2 C142.2 C144.2 C151.2 C152.2 C153.2 C158.2 C159.2 C160.2 C161.2 C162.2 C163.2 C169.2 C170.2 C171.2 C172.2 C184.2 C185.2 C189.2 C190.2 C195.2 C196.2 C199.2 C200.2 C217.2 C218.2 C219.2 C220.2 C221.2 C222.2 C223.2 C224.2 C225.2 C226.2 C227.2 C237.2 C240.2 C242.2 C243.2 C245.2 C246.2 C247.2 C248.2 C249.2 C250.2 C252.2 C253.2 C255.2 C258.2 C260.2 C263.2 C265.2 C267.2 C270.2 C271.2 C281.2 C282.2 C283.2 C284.2 C285.2 C289.2 C325.2 C331.2 C332.2 C335.2 C340.2 C344.2 C345.2 C351.2 C404.2 C405.2 C411.2 C446.2 C447.2 C448.2 C472.2 C479.2 C503.2 C532.2 C536.2 C546.2 C565.2 C566.2 C567.2 C568.2 C575.2 C581.2 C582.2 C585.2 C586.2 C592.2 C593.2 C595.2 C596.2 C615.2 C616.2 C630.2 C631.2 C636.2 C637.2 C644.2 C645.2 C649.2 C650.2 C664.2 C665.2 C666.2 C667.2 C668.2 C669.2 C670.2 C671.2 C672.2 C673.2 C674.2 C675.2 C676.2 C677.2 C678.2 C679.2 J1.5(USBVSS) J1.6(SHIELD1) J1.7(SHIELD2) J1.8(SHIELD3) J1.9(SHIELD4) J2.1 J2.2 J2.3 J16.1 J16.2 J16.3 P2.5(USBVSS) P2.8(CON8) P2.11(SHIELD1) P2.12(SHIELD2) P2.13(SHIELD3) P2.14(SHIELD4) P2.15(SHIELD5) P2.16(SHIELD6) P3.5(USBVSS) P3.6(SHIELD1) P3.7(SHIELD2) P3.8(SHIELD3) P3.9(SHIELD4) P5.1(GND) P5.11(SHLD1) P5.12(SHLD2) P5.D4(LED2-KA) P6.1(GND) P6.11(SHLD1) P6.12(SHLD2) P6.D4(LED2-KA) P9.2 P9.3 P9.6 P9.9 P9.18 P9.19 P9.22 P9.37 P9.42 P9.47 P9.60 P9.63 P9.64 P9.77 P9.83 P9.87 P9.92 P9.95 P9.97 P10.1(SHIELD) P10.4(TIPB) P11.1(SHIELD) P11.4(TIPB) P12.1(SHIELD) P13.1(SHIELD) R28.1 R30.1 R33.1 R39.1 R41.1 R44.1 R47.1 R50.1 R52.1 R55.1 R66.1 R68.2 R74.2 R96.1 R107.2 R108.1 R109.1 R154.2 R157.2 R178.2 R179.2 R196.2 R200.2 R241.2 R257.2 R260.2 R262.2 R266.2 R287.2 R300.1 R303.1 R306.1 R308.1 R323.2 R325.2 R348.1 R349.1 R354.1 R358.1 R360.1 R363.1 R366.1 R369.1 R371.1 R374.1 R380.1 R384.2 R386.2 R399.2 R408.1 R441.1 R446.2 R447.1 R479.2 R481.1 R515.2 R532.1 R539.1 R568.1 R642.2 R643.2 R644.2 R675.2 R696.2 R701.2 R702.2 R714.1 R715.2 RU5.8(GND) RU5.10(3B2) RU5.11(3B1) RU5.13(4B2) RU5.14(4B1) RU5.15(~{OE}) U2.4(GND.1) U2.17(GND.2) U2.20(GND.3) U2.24(AGND) U2.26(TEST) U2.33(PWRPAD) U7.5(VSS) U7.12(VSS) U7.16(VSS) U7.17(PHYAD2_STRAP) U7.18(PHYAD3_STRAP) U7.20(VSS) U7.22(VSS) U7.26(VSS) U7.30(VSS) U7.36(VSS) U7.38(VSS) U7.43(VSS) U7.49(VSS) U7.54(VSS) U7.59(VSS) U7.64(VSS) U7.70(VSS) U7.74(VSS) U7.78(VSS) U7.82(VSS) U7.91(VSS) U7.93(VSS) U7.95(PHYAD4_STRAP) U7.97(VSS) U7.99(VSS) U7.104(VSS) U7.106(VSS) U7.107(VSS) U7.110(VSS) U7.112(VSS) U7.113(VSS) U7.116(VSS) U7.118(VSS) U7.119(VSS) U7.122(VSS) U7.124(VSS) U7.125(VSS) U7.128(VSS) U10.3(GND) U15.3(GND) U35.2(DIR) U35.11(GND) U35.12(GND) U35.13(GND) U35.25(PP) U36.1(GND) U41.7(2A2) U41.8(GND.1) U41.9(GND.2) U41.17(GND.3) U43.1(GND) U46.11(GND) U46.12(GND) U46.13(GND) U46.25(PP) U48.7(2A2) U48.8(GND.1) U48.9(GND.2) U48.17(GND.3) U50.1(GND) U55.2(GND) U55.3(ENn) U56.6(GND) U56.11(PP1) U59.15(AVSS_ADC) U59.20(DRVSS.1) U59.21(DRVSS.2) U59.26(AVSS_DAC) U59.42(DVSS) U59.49(TPAD) U72.8(GND) U72.11(PWR_PAD) U73.8(GND) U73.11(PWR_PAD) U84.5(VSS) U84.12(VSS) U84.16(VSS) U84.17(PHYAD2_STRAP) U84.18(PHYAD3_STRAP) U84.20(VSS) U84.22(VSS) U84.26(VSS) U84.30(VSS) U84.36(VSS) U84.38(VSS) U84.43(VSS) U84.49(VSS) U84.54(VSS) U84.59(VSS) U84.64(VSS) U84.70(VSS) U84.74(VSS) U84.78(VSS) U84.82(VSS) U84.91(VSS) U84.93(VSS) U84.95(PHYAD4_STRAP) U84.97(VSS) U84.99(VSS) U84.104(VSS) U84.106(VSS) U84.107(VSS) U84.110(VSS) U84.112(VSS) U84.113(VSS) U84.116(VSS) U84.118(VSS) U84.119(VSS) U84.122(VSS) U84.124(VSS) U84.125(VSS) U84.128(VSS) U85.3(GND) U100.11(GND1) U100.17(B3) U100.18(B2) U100.20(B1) U104.2(GND) U104.5(DIR) U124.2(GND) U125.2(GND) U126.2(GND) U127.2(GND) ; also on sheet 3 4 5 7 8 9 10 11 13 15 16 17 18 19 20 21 24 25 26 27 28 29 30 31 32 33 34 35 36 37 38 39 40 42 43 46 60 61 62 63 64 65 66 67 68 69 70 71 72 73 74 75 77 79 80 81 84 85 86 87 88 89
VDD_DDR: C158.1 C159.1 C160.1 C161.1 C162.1 C163.1 C166.2 C167.2 C169.1 C170.1 C171.1 C172.1 C176.2 C181.2 C184.1 C185.1 C189.1 C190.1 C195.1 C196.1 C199.1 C200.1 C208.2 C209.2 C581.1 C582.1 C585.1 C586.1 C592.1 C593.1 C595.1 C596.1 C601.2 C615.1 C616.1 C626.2 C630.1 C631.1 C634.2 C636.1 C637.1 C642.2 C644.1 C645.1 C649.1 C650.1 C653.2 C660.2 C661.2 C664.1 C665.1 C666.1 C667.1 C668.1 C669.1 C670.1 C671.1 C672.1 C673.1 C674.1 C675.1 C676.1 C677.1 C678.1 C679.1 ; also on sheet 42 43 44 46 73 81
AIC3106_I2C_0x19: R257.1 R654.2 U59.45(MFP0) ; also on sheet 63
AIC3106_MCLK: R254.1 ; also on sheet 2
AIC_AVDD_DAC3.3: C141.1 C142.1 C144.1 L21.1 U59.25(AVDD_DAC)
AIC_BCLK: R253.2 R642.1 U59.38(BCLK)
AIC_DIN: R251.2 R643.1 U59.40(DIN)
AIC_DOUT: R250.2 U59.41(DOUT)
AIC_DRVDD3.3: C151.1 C152.1 C565.1 C566.1 C567.1 L22.1 U59.16(DRVDD.1) U59.17(DRVDD.2) U59.24(DRVDD.3)
AIC_DVDD3.3: C133.1 C134.1 U55.5(OUT) U59.36(DVDD.1)
AIC_IOVDD3.3: C130.1 C132.1 L19.2 U59.44(IOVDD)
AIC_MCA3_ACLKX: R253.1 ; also on sheet 86
AIC_MCA3_AFSX: R252.1 ; also on sheet 86
AIC_MCA3_AXR0: R251.1 ; also on sheet 86
AIC_MCA3_AXR1: R250.1 ; also on sheet 86
AIC_WCLK: R252.2 U59.39(WCLK)
BT_EN: P9.89 U46.20(B2)
BT_UART_CTS: P9.70 U46.15(B7)
BT_UART_RTS: P9.72 U35.16(B6)
BT_UART_RX: P9.68 U46.14(B8)
BT_UART_TX: P9.66 U35.17(B5)
COMQ_MMC0_CLK: P9.20 U104.3(A)
COMQ_MMC0_CMD: P9.24 R559.2 U100.5(A4)
COMQ_MMC0_DAT0: P9.26 R560.2 U100.6(A5)
COMQ_MMC0_DAT1: P9.28 R561.2 U100.7(A6)
COMQ_MMC0_DAT2: P9.30 R562.2 U100.8(A7)
COMQ_MMC0_DAT3: P9.32 R558.2 U100.9(A8)
CON_P0_ACTIVITY: P5.D3(LED2-AK) R299.1
CON_P0_LINK: P5.D2(LED1-K) R295.2 R298.1
CON_P1_ACTIVITY: P6.D3(LED2-AK) R297.1
CON_P1_LINK1: P6.D2(LED1-K) R294.2 R296.1
CONN_USB1_DM: FL1.3 P2.2(D-) U73.6(D-)
CONN_USB1_DP: FL1.2 P2.3(D+) U73.7(D+)
CONN_USB2_DM: FL4.3 P3.2(D-) U72.6(D-)
CONN_USB2_DP: FL4.2 P3.3(D+) U72.7(D+)
CONN_USB_D+: J1.3(D+) U2.14(USBDP)
CONN_USB_D-: J1.2(D-) U2.15(USBDM)
CONN_USB_RXN0: FL3.3 P2.9(CON9) U124.1(IO)
CONN_USB_RXP0: FL3.2 P2.10(CON10) U125.1(IO)
CONN_USB_TXN0: FL2.3 P2.6(CON6) U126.1(IO)
CONN_USB_TXP0: FL2.2 P2.7(CON7) U127.1(IO)
DDR2_A0: RN14.1(R1A) ; also on sheet 20 45 46
DDR2_A1: RN16.4(R4A) ; also on sheet 20 45 46
DDR2_A2: RN5.3(R3A) ; also on sheet 20 45 46
DDR2_A3: RN5.1(R1A) ; also on sheet 20 45 46
DDR2_A4: RN5.4(R4A) ; also on sheet 20 45 46
DDR2_A5: RN5.2(R2A) ; also on sheet 20 45 46
DDR2_A6: RN7.3(R3A) ; also on sheet 20 45 46
DDR2_A7: RN16.3(R3A) ; also on sheet 20 45 46
DDR2_A8: RN16.1(R1A) ; also on sheet 20 45 46
DDR2_A9: RN7.1(R1A) ; also on sheet 20 45 46
DDR2_A10: RN3.1(R1A) ; also on sheet 20 45 46
DDR2_A11: RN7.2(R2A) ; also on sheet 20 45 46
DDR2_A12: RN14.3(R3A) ; also on sheet 20 45 46
DDR2_A13: RN16.2(R2A) ; also on sheet 20 45 46
DDR2_A14: RN7.4(R4A) ; also on sheet 20 45 46
DDR2_A15: RN3.3(R3A) ; also on sheet 20 45 46
DDR2_BA0: RN12.3(R3A) ; also on sheet 20 45 46
DDR2_BA1: RN14.2(R2A) ; also on sheet 20 45 46
DDR2_BA2: RN14.4(R4A) ; also on sheet 20 45 46
DDR2_CASN: RN12.2(R2A) ; also on sheet 20 45 46
DDR2_CKE: R830.1 ; also on sheet 20 45 46
DDR2_CLK0: R685.1 ; also on sheet 20 45 46
DDR2_CLK0N: R688.1 ; also on sheet 20 45 46
DDR2_CSN0: RN12.1(R1A) ; also on sheet 20 45 46
DDR2_ODT0: RN3.2(R2A) ; also on sheet 20 45 46
DDR2_RASN: R286.1 ; also on sheet 20 45 46
DDR2_WEN: RN3.4(R4A) ; also on sheet 20 45 46
EMAC[0]_RXC: R103.1 ; also on sheet 85
EMAC[0]_RXCTL: R102.1 ; also on sheet 85
EMAC[0]_RXD0: RN1.8(R1B) ; also on sheet 85
EMAC[0]_RXD1: RN1.7(R2B) ; also on sheet 85
EMAC[0]_RXD2: RN1.6(R3B) ; also on sheet 85
EMAC[0]_RXD3: RN1.5(R4B) ; also on sheet 85
EMAC[0]_TXC: U7.79(GTX_CLK_/_RGMII_TCK) ; also on sheet 85
EMAC[0]_TXCTL: U7.62(TX_EN_/_RGMII_TXEN_ER) ; also on sheet 85
EMAC[0]_TXD0: U7.76(TXD0_/_RGMII_TX0) ; also on sheet 85
EMAC[0]_TXD1: U7.75(TXD1_/_RGMII_TX1) ; also on sheet 85
EMAC[0]_TXD2: U7.72(TXD2_/_RGMII_TX2) ; also on sheet 85
EMAC[0]_TXD3: U7.71(TXD3_/_RGMII_TX3) ; also on sheet 85
EMAC[1]_RXC: R438.1 ; also on sheet 25
EMAC[1]_RXCTL: R437.1 ; also on sheet 25
EMAC[1]_RXD0: RN11.8(R1B) ; also on sheet 25
EMAC[1]_RXD1: RN11.7(R2B) ; also on sheet 25
EMAC[1]_RXD2: RN11.6(R3B) ; also on sheet 25
EMAC[1]_RXD3: RN11.5(R4B) ; also on sheet 25
EMAC[1]_TXC: U84.79(GTX_CLK_/_RGMII_TCK) ; also on sheet 25
EMAC[1]_TXCTL: U84.62(TX_EN_/_RGMII_TXEN_ER) ; also on sheet 25
EMAC[1]_TXD0: U84.76(TXD0_/_RGMII_TX0) ; also on sheet 25
EMAC[1]_TXD1: U84.75(TXD1_/_RGMII_TX1) ; also on sheet 25
EMAC[1]_TXD2: U84.72(TXD2_/_RGMII_TX2) ; also on sheet 25
EMAC[1]_TXD3: U84.71(TXD3_/_RGMII_TX3) ; also on sheet 25
ENET_1V8: C27.1 C28.1 C34.1 C40.1 C44.1 C48.1 C53.1 C57.1 C58.1 C247.1 C248.1 C253.1 C260.1 C267.1 C271.1 C281.1 C283.1 C289.1 R26.2 R32.2 R347.2 R352.2 U7.11(CORE_VDD) U7.19(CORE_VDD) U7.25(CORE_VDD) U7.35(CORE_VDD) U7.48(CORE_VDD) U7.63(CORE_VDD) U7.73(CORE_VDD) U7.92(CORE_VDD) U7.103(1V8_AVDD1) U7.105(1V8_AVDD1) U7.111(1V8_AVDD1) U7.117(1V8_AVDD1) U7.123(1V8_AVDD1) U84.11(CORE_VDD) U84.19(CORE_VDD) U84.25(CORE_VDD) U84.35(CORE_VDD) U84.48(CORE_VDD) U84.63(CORE_VDD) U84.73(CORE_VDD) U84.92(CORE_VDD) U84.103(1V8_AVDD1) U84.105(1V8_AVDD1) U84.111(1V8_AVDD1) U84.117(1V8_AVDD1) U84.123(1V8_AVDD1) ; also on sheet 69
ENET_INT_P2: R357.2 U15.2(A) U84.3(INTERRUPT_N)
ENET_INTSn: R765.1 ; also on sheet 87
ENET_PORz: U10.1(B) U85.1(B) ; also on sheet 33
EVM_1V8: P9.8 R548.1 R600.1 ; also on sheet 8 10 26 61 69 74
EVM_2V5: R21.2 R339.2 ; also on sheet 69
EVM_3V3: C32.1 C37.1 C41.1 C43.1 C46.1 C54.1 C55.1 C56.1 C59.1 C249.1 C252.1 C255.1 C263.1 C265.1 C270.1 C282.1 C284.1 C285.1 C331.1 C344.1 C351.1 C404.1 C446.1 C479.1 P5.D1(LED1-A) P6.D1(LED1-A) R1.2 R2.2 R31.1 R34.1 R36.1 R40.1 R42.1 R43.1 R48.1 R49.2 R53.1 R54.2 R61.2 R67.2 R72.1 R73.1 R97.1 R100.2 R101.2 R105.2 R301.2 R302.2 R307.2 R324.1 R326.1 R350.1 R355.1 R357.1 R359.1 R361.1 R362.1 R367.1 R368.2 R372.1 R373.2 R378.2 R382.2 R409.1 R432.2 R435.2 R436.2 R519.1 R520.1 R521.1 R522.1 R523.1 R524.1 R528.1 R536.2 R581.1 R584.1 R587.1 R603.1 R770.2 R771.2 RU5.16(VCC) U7.4(IO_VDD) U7.15(IO_VDD) U7.21(IO_VDD) U7.29(IO_VDD) U7.37(IO_VDD) U7.42(IO_VDD) U7.53(IO_VDD) U7.58(IO_VDD) U7.69(IO_VDD) U7.77(IO_VDD) U7.83(IO_VDD) U7.90(IO_VDD) U10.5(VCC) U15.5(VCC) U35.1(VCCA) U41.1(VCCA) U46.1(VCCA) U46.2(DIR) U48.1(VCCA) U84.4(IO_VDD) U84.15(IO_VDD) U84.21(IO_VDD) U84.29(IO_VDD) U84.37(IO_VDD) U84.42(IO_VDD) U84.53(IO_VDD) U84.58(IO_VDD) U84.69(IO_VDD) U84.77(IO_VDD) U84.83(IO_VDD) U84.90(IO_VDD) U85.5(VCC) U100.19(VCCB) U104.6(VCCB) ; also on sheet 3 4 5 7 8 9 10 11 14 15 16 17 18 24 25 26 27 28 29 30 31 32 33 60 61 69 70 78 84 85 86 87 88
EVM_3V6: C503.1 C515.1 P9.5 P9.7 R244.1 U56.9(VOUT1) U56.10(VOUT2)
EVM_5V0: C325.1 C340.1 C546.1 U36.2(IN1) U36.3(IN2) U43.2(IN1) U43.3(IN2) U56.1(IN1) U56.2(IN2) U56.4(BIAS) U56.5(EN) ; also on sheet 3 26 27 29 31 61 78
EXP_ETH0_RSTn: U10.2(A) ; also on sheet 9
EXP_ETH1_RSTn: U85.2(A) ; also on sheet 9
FM_I2S_CLK: P9.49 U48.13(1B1)
FM_I2S_DI: P9.53 U48.11(2B1)
FM_I2S_DO: P9.51 U35.18(B4)
FM_I2S_FSYNC: P9.55 U48.12(1B2)
FTDI_UARTIN: RU5.4(1A) U2.2(RXD)
FTDI_UARTOUT: RU5.7(2A) U2.30(TXD)
GP5[4]: U46.4(A2) ; also on sheet 2
GP5[5]: U35.5(A3) ; also on sheet 2
GP5[6]: U46.6(A4) ; also on sheet 2
GP5[7]: U35.3(A1) ; also on sheet 2
GP5[8]: U46.5(A3) ; also on sheet 2
GPS_PPS_OUT: P9.50 U35.19(B3)
GPS_TIME_STAMP: P9.48 U46.18(B4)
I2C1_SCL: U50.6(SCL2) U59.1(SCL) ; also on sheet 9 11 26 61 87 88
I2C1_SDA: U50.5(SDA2) U59.2(SDA) ; also on sheet 9 11 26 61 87 88
LVL_SHIFT_V: C332.1 C335.1 C345.1 C405.1 C411.1 C447.1 C448.1 C472.1 R536.1 R548.2 R558.1 R559.1 R560.1 R561.1 R562.1 U35.23(VCCB) U35.24(VCCB) U41.16(VCCB) U46.23(VCCB) U46.24(VCCB) U48.16(VCCB) U100.2(VCCA) U100.10(OE) U104.1(VCCA)
MCA1_ACLKX: U48.4(1A1) ; also on sheet 86
MCA1_AFSX: U48.5(1A2) ; also on sheet 86
MCA1_AXR0: U35.6(A4) ; also on sheet 86
MCA1_AXR1: U48.6(2A1) ; also on sheet 86
MCA7_AXR0: U35.9(A7) ; also on sheet 86
MCA7_AXR1: U41.6(2A1) ; also on sheet 86
MCA7_CLKX: U41.4(1A1) ; also on sheet 86
MCA7_FSX: U41.5(1A2) ; also on sheet 86
MCASP1_ENn: R479.1 R539.2 R568.2 U35.22(OEn) U46.22(OEn) U48.14(2~{OE}) U48.15(1~{OE}) ; also on sheet 9 18
MDIO_MDCLK: R72.2 U7.81(MDC) U84.81(MDC) ; also on sheet 85
MDIO_MDIO: R73.2 U7.80(MDIO) U84.80(MDIO) ; also on sheet 85
MMC4_CLK: R587.2 U104.4(B) ; also on sheet 87
MMC4_CMD: R520.2 U100.16(B4) ; also on sheet 87
MMC4_DAT0: R521.2 U100.15(B5) ; also on sheet 87
MMC4_DAT1: R522.2 U100.14(B6) ; also on sheet 87
MMC4_DAT2: R523.2 U100.13(B7) ; also on sheet 87
MMC4_DAT3: R524.2 U100.12(B8) ; also on sheet 87
P0_LED_ACT: R39.2 R40.2 R299.2 U7.7(ACT_LED_/_SPEED0_STRAP)
P0_LED_LINK10_100: R47.2 R48.2 R295.1 U7.9(LINK100_LED_/_DUPLEX_STRAP)
P0_LED_LINK1000: R52.2 R53.2 R298.2 U7.10(LINK1000_LED_/_AN_EN_STRAP)
P0_TRD[0]N: P5.10(T0-) R329.1 U7.109(MDIA_N)
P0_TRD[0]P: P5.9(T0+) R331.1 U7.108(MDIA_P)
P0_TRD[1]N: P5.8(T1-) R320.1 U7.115(MDIB_N)
P0_TRD[1]P: P5.7(T1+) R319.1 U7.114(MDIB_P)
P0_TRD[2]N: P5.6(T2-) R318.1 U7.121(MDIC_N)
P0_TRD[2]P: P5.5(T2+) R317.1 U7.120(MDIC_P)
P0_TRD[3]N: P5.4(T3-) R316.1 U7.127(MDID_N)
P0_TRD[3]P: P5.3(T3+) R315.1 U7.126(MDID_P)
P1_LED_ACT: R297.2 R358.2 R359.2 U84.7(ACT_LED_/_SPEED0_STRAP)
P1_LED_LINK10_100: R294.1 R366.2 R367.2 U84.9(LINK100_LED_/_DUPLEX_STRAP)
P1_LED_LINK1000: R296.2 R371.2 R372.2 U84.10(LINK1000_LED_/_AN_EN_STRAP)
P1_TRD[0]N: P6.10(T0-) R328.1 U84.109(MDIA_N)
P1_TRD[0]P: P6.9(T0+) R330.1 U84.108(MDIA_P)
P1_TRD[1]N: P6.8(T1-) R314.1 U84.115(MDIB_N)
P1_TRD[1]P: P6.7(T1+) R313.1 U84.114(MDIB_P)
P1_TRD[2]N: P6.6(T2-) R312.1 U84.121(MDIC_N)
P1_TRD[2]P: P6.5(T2+) R311.1 U84.120(MDIC_P)
P1_TRD[3]N: P6.4(T3-) R310.1 U84.127(MDID_N)
P1_TRD[3]P: P6.3(T3+) R309.1 U84.126(MDID_P)
PCM_CLK: P9.52 U41.13(1B1)
PCM_DIN: P9.56 U41.11(2B1)
PCM_DOUT: P9.58 U35.15(B7)
PCM_FSYNC: P9.54 U41.12(1B2)
PHY0_2V5: C17.1 C20.1 C26.1 C221.1 C222.1 C223.1 C225.1 C227.1 P5.2(VCC) R21.1 R315.2 R316.2 R317.2 R318.2 R319.2 R320.2 R329.2 R331.2 U7.96(2V5_AVDD2) U7.101(2V5AVDD1)
PHY1_2V5: C218.1 C219.1 C220.1 C224.1 C226.1 C237.1 C240.1 C246.1 P6.2(VCC) R309.2 R310.2 R311.2 R312.2 R313.2 R314.2 R328.2 R330.2 R339.1 U84.96(2V5_AVDD2) U84.101(2V5AVDD1)
PMIC_32K_CLKOUT: R222.1 ; also on sheet 63
R_EMAC[0]_RXC: R103.2 U7.44(RX_DV_/_RGMII_RCK)
R_EMAC[0]_RXCTL: R102.2 U7.41(RX_ER_/_RGMII_RXDV_ER)
R_EMAC[0]_RXD0: RN1.1(R1A) U7.56(RXD0_/_RGMII_RX0)
R_EMAC[0]_RXD1: RN1.2(R2A) U7.55(RXD1_/_RGMII_RX1)
R_EMAC[0]_RXD2: RN1.3(R3A) U7.52(RXD2_/_RGMII_RX2)
R_EMAC[0]_RXD3: RN1.4(R4A) U7.51(RXD3_/_RGMII_RX3)
R_EMAC[1]_RXC: R438.2 U84.44(RX_DV_/_RGMII_RCK)
R_EMAC[1]_RXCTL: R437.2 U84.41(RX_ER_/_RGMII_RXDV_ER)
R_EMAC[1]_RXD0: RN11.1(R1A) U84.56(RXD0_/_RGMII_RX0)
R_EMAC[1]_RXD1: RN11.2(R2A) U84.55(RXD1_/_RGMII_RX1)
R_EMAC[1]_RXD2: RN11.3(R3A) U84.52(RXD2_/_RGMII_RX2)
R_EMAC[1]_RXD3: RN11.4(R4A) U84.51(RXD3_/_RGMII_RX3)
RSTOUTn: R5.2 U59.33(~{RESET}) ; also on sheet 4 7 8 11 29 30 33 63
SLEEP_CLK: P9.1 R222.2
UART1_RXD: RU5.5(2B1) ; also on sheet 87
UART1_TXD: RU5.2(1B1) ; also on sheet 87
UART3_CTS: U35.8(A6) ; also on sheet 84
UART3_RTS: U46.9(A7) ; also on sheet 84
UART3_RXD: U35.7(A5) ; also on sheet 84
UART3_RXD_BOOT: RU5.6(2B2) ; also on sheet 87
UART3_TXD: U46.10(A8) ; also on sheet 84
UART3_TXD_BOOT: RU5.3(1B2) ; also on sheet 87
UART_SEL1_3: R384.1 RU5.1(S) ; also on sheet 9 18
USB1_DM: FL1.4 ; also on sheet 13
USB1_DP: FL1.1 ; also on sheet 13
USB1_DRV_VBUS: R481.2 U36.4(EN) ; also on sheet 13
USB1_ID: P2.4(ID) R326.2 SW1.2(A2) U73.5(ID) ; also on sheet 9
USB1_VBUS: C80.1 L8.1 P2.1(USBVDD) U73.9(VBUS.2) U73.10(VBUS.1)
USB1_VBUS_OCN: R771.1 TP27.1 U36.5(OCn) ; also on sheet 9
USB2_DM: FL4.4 ; also on sheet 13
USB2_DP: FL4.1 ; also on sheet 13
USB2_DRV_VBUS: R532.2 U43.4(EN) ; also on sheet 13
USB2_ID: P3.4(ID) R324.2 SW1.1(A1) U72.5(ID) ; also on sheet 9
USB2_VBUS: C87.1 C217.1 L12.1 P3.1(USBVDD) U72.9(VBUS.2) U72.10(VBUS.1) ; also on sheet 2
USB2_VBUS_OCN: R770.1 TP39.1 U43.5(OCn) ; also on sheet 9
USB_AC_TXN0: C682.2 FL2.4
USB_AC_TXP0: C681.2 FL2.1
USB_RXN0: FL3.4 ; also on sheet 13
USB_RXP0: FL3.1 ; also on sheet 13
USB_TXN0: C682.1 ; also on sheet 13
USB_TXP0: C681.1 ; also on sheet 13
VDAC_3V3: C131.1 C153.1 C536.1 L19.1 L21.2 L22.2 R249.1 R654.1 R659.1 R664.1 R668.1 U55.1(IN) ; also on sheet 63 77
VTT: C166.1 C167.1 C176.1 C181.1 C208.1 C209.1 C626.1 C634.1 C642.1 C653.1 C660.1 C661.1 R286.2 R830.2 RN3.5(R4B) RN3.6(R3B) RN3.7(R2B) RN3.8(R1B) RN5.5(R4B) RN5.6(R3B) RN5.7(R2B) RN5.8(R1B) RN7.5(R4B) RN7.6(R3B) RN7.7(R2B) RN7.8(R1B) RN12.5(R4B) RN12.6(R3B) RN12.7(R2B) RN12.8(R1B) RN14.5(R4B) RN14.6(R3B) RN14.7(R2B) RN14.8(R1B) RN16.5(R4B) RN16.6(R3B) RN16.7(R2B) RN16.8(R1B) ; also on sheet 44 70
WL_EN: P9.4 U46.19(B3)
WLAN_IRQ: P9.34 U35.21(B1)
N16995143: R593.1 R597.1 R600.2 U50.2(VREF1)
N17024050: R178.1 R528.2 U41.2(1DIR)
N17024419: R157.1 R519.2 U41.3(2DIR)
N17038912: R200.1 R584.2 U48.2(1DIR)
N17039180: R196.1 R581.2 U48.3(2DIR)
N17041540: R715.1 U35.14(B8) U35.20(B2)
N17041657: R714.2 U46.3(A1) U46.7(A5) U46.8(A6)
N19054608: R74.1 U7.32(TRST_N)
N19184134: P9.12 TP49.1(TP)
N19184365: P9.14 TP46.1(TP)
N19184698: P9.16 TP44.1(TP)
N19185088: P9.73 TP23.1(TP)
N19220553: R765.2 U15.4(Y)
N20019184: C601.1 R685.2 R688.2
N21135838: C646.1 U59.23(HPROUT)
N21135844: C646.2 P13.3(RING) R701.1
N21135850: C620.2 P13.2(TIP) R696.1
N21135862: C620.1 U59.18(HPLOUT)
N21135894: C647.2 P12.3(RING) R702.1
N21136021: R249.2 R644.1 U59.43(SELECT)
N21136029: R671.2 U59.11(MIC3L) U59.14(MIC3R)
N21136035: C558.1 C575.1 P10.2(TIP) P10.3(RING) R673.1 R675.1
N21136037: C568.1 R672.1 R673.2
N21136043: R672.2 U59.13(MICBIAS)
N21136051: C558.2 R671.1
N21136104: C173.2 U59.3(LINE1L+)
N21136106: C168.2 P12.2(TIP) R287.1
N21136108: C648.2 U59.5(LINE1R+)
N21136118: R281.1 U59.29(LEFT_LO+)
N21136820: C648.1 P11.3(RING)
N21136923: R260.1 R659.2 U59.46(MFP1)
N21136925: R262.1 R664.2 U59.47(MFP2)
N21136935: R254.2 U59.37(MCLK)
N21136951: R266.1 R668.2 U59.48(MFP3)
N21137001: C173.1 P11.2(TIP)
N21137040: C647.1 R697.2
N21137042: R697.1 U59.31(RIGHT_LO+)
N21137044: C168.1 R281.2
N22206221: P9.76 TP22.1(TP)
N22223983: P9.11 TP48.1(TP)
N22225609: P9.13 TP47.1(TP)
N22227190: P9.15 TP45.1(TP)
N22557684: C10.1 C11.1 R2.1 R3.1 R4.1 U2.1(VCCIO.1)
N22559209: R3.2 U2.16(3V3OUT)
N22562266: R4.2 U2.11(CBUS3)
N22573042: C4.1 C9.1 L1.2 U2.19(VCC)
N22663792: C2.1 J1.1(USBVDD) L1.1
N22754009: C79.1 L8.2 R154.1 U36.6(OUT3) U36.7(OUT2) U36.8(OUT1)
N23472706: R36.2 U7.3(INTERRUPT_N) U15.1(B)
N23525508: C22.1 C25.1 R32.1 U7.98(1V8_AVDD2)
N25164864: C532.1 U56.7(SS)
N25164868: C515.2 R241.1 R244.2 U56.8(FB)
N25214719: R603.2 U50.7(VREF2) U50.8(EN)
N27717584: TP1.1 U72.1(VBUS_OUT.1) U72.2(VBUS_OUT.2)
N27837506: R300.2 R301.1 U73.4(ACKn)
N27843210: R1.1 R308.2 U73.3(ENn)
N27851964: R302.1 R303.2 U72.3(ENn)
N27851968: R306.2 R307.1 U72.4(ACKn)
N28338968: R515.1 U41.14(2~{OE}) U41.15(1~{OE})
N30072455: R5.1 U2.18(RESET#)
N32582765: TP2.1 U73.1(VBUS_OUT.1) U73.2(VBUS_OUT.2)
N32636865: R325.1 SW1.3(A3)
N32636901: R323.1 SW1.4(A4)
N32675681: C86.1 L12.2 R179.1 U43.6(OUT3) U43.7(OUT2) U43.8(OUT1)
N38185032: C33.1 R69.1 U7.87(CLOCK_OUT) Y1.2
N38185040: C38.1 R69.2 U7.86(CLOCK_IN) Y1.1
N38676132: R105.1 R109.2 U7.60(TX_CLK_/_RGMII_SEL1)
N38679060: R101.1 R108.2 U7.40(CRS_/_RGMII_SEL0)
N38681990: R100.1 R107.1 U7.39(COL_/_CLK_MAC_FREQ)
N39292206: U7.33(RESET_N) U10.4(Y)
N39376605: C258.1 R387.2 U84.86(CLOCK_IN) Y7.1
N39376607: C250.1 R387.1 U84.87(CLOCK_OUT) Y7.2
N39425958: R67.1 R68.1 U7.14(PHYAD1_STRAP)
N39425964: R61.1 R66.2 U7.13(DUPLEX_LED_/_PHYAD0_STRAP)
N39466189: R28.2 U7.102(BG_REF)
N39756933: R49.1 R50.2 U7.89(MDIX_EN_STRAP)
N39759955: R43.2 R44.2 U7.94(TX_TRIGGER_/_MULTI_EN_STRAP)
N39762978: R54.1 R55.2 U7.88(MAC_CLK_EN_STRAP)
N39766004: R33.2 R34.2 U7.6(TX_TCLK_/_MAN_MDIX_STRAP)
N39769032: R30.2 R31.2 U7.1(NON_IEEE_STRAP)
N39772061: R96.2 R97.2 U7.34(VDD_SEL_STRAP)
N39816182: R41.2 R42.2 U7.8(LINK10_LED_/_RLED_/_SPEED1_STRAP)
N40695905: R360.2 R361.2 U84.8(LINK10_LED_/_RLED_/_SPEED1_STRAP)
N40695981: R349.2 R350.2 U84.1(NON_IEEE_STRAP)
N40696020: R432.1 R441.2 U84.60(TX_CLK_/_RGMII_SEL1)
N40696024: R354.2 R355.2 U84.6(TX_TCLK_/_MAN_MDIX_STRAP)
N40696072: R436.1 R447.2 U84.40(CRS_/_RGMII_SEL0)
N40696102: R373.1 R374.2 U84.88(MAC_CLK_EN_STRAP)
N40696104: R362.2 R363.2 U84.94(TX_TRIGGER_/_MULTI_EN_STRAP)
N40696106: R368.1 R369.2 U84.89(MDIX_EN_STRAP)
N40696168: C243.1 C245.1 R352.1 U84.98(1V8_AVDD2)
N40696230: R378.1 R380.2 U84.13(DUPLEX_LED_/_PHYAD0_STRAP)
N40696232: R382.1 R386.1 U84.14(PHYAD1_STRAP)
N40696356: R435.1 R446.1 U84.39(COL_/_CLK_MAC_FREQ)
N40696514: U84.33(RESET_N) U85.4(Y)
N40696690: R408.2 R409.2 U84.34(VDD_SEL_STRAP)
N40697542: R399.1 U84.32(TRST_N)
N40697566: R348.2 U84.102(BG_REF)
N41583956: C21.1 R26.1 U7.100(1V8_AVDD3)
N41669339: C242.1 R347.1 U84.100(1V8_AVDD3)

Not connected (* = marked no-connect by the designer): J1 4(ID)*; P9 10* 17* 21* 23* 25* 27* 29* 35* 36* 38* 39* 40* 41* 43* 44* 45* 46* 57* 59* 61* 62* 65* 67* 69* 71* 74* 75* 78* 79* 80* 81* 82* 84* 85* 86* 88* 90* 91* 93* 94* 96* 98* 99* 100*; P10 5(MH1) 6(MH2); P11 5(MH1) 6(MH2); P12 4(TIPB) 5(MH1) 6(MH2); P13 4(TIPB) 5(MH1) 6(MH2); RN12 4(R4A); RU5 9(3A) 12(4A); U2 3(RIn)* 5(NC.5)* 6(DSRn)* 7(DCDn)* 8(CTS#) 9(CBUS4)* 10(CBUS2)* 12(NC.12)* 13(NC.13)* 21(CBUS1)* 22(CBUS0)* 23(NC.23)* 25(NC.25)* 27(OSCI)* 28(OSCO)* 29(NC.29)* 31(DTR#)* 32(RTS#); U7 2(NC.2) 23(NC.23) 24(TCK) 27(TMS) 28(TDO) 31(TDI) 45(RXD7) 46(RXD6) 47(RXD5) 50(RXD4) 57(RX_CLK) 61(TX_ER) 65(TXD7) 66(TXD6) 67(TXD5) 68(TXD4) 84(NC.84) 85(CLK_TO_MAC); U35 4(A2) 10(A8); U41 10(2B2); U46 16(B6) 17(B5) 21(B1); U48 10(2B2); U55 4(NC/FB)*; U56 3(PG); U59 4(LINE1L-) 6(LINE1R-) 7(LINE2L+) 8(LINE2L-) 9(LINE2R+) 10(LINE2R-) 12(MICDET) 19(HPLCOM) 22(HPRCOM) 27(MONO_LO+) 28(MONO_LO-) 30(LEFT_LO-) 32(RIGHT_LO-) 34(GPIO2) 35(GPIO1); U84 2(NC.2) 23(NC.23) 24(TCK) 27(TMS) 28(TDO) 31(TDI) 45(RXD7) 46(RXD6) 47(RXD5) 50(RXD4) 57(RX_CLK) 61(TX_ER) 65(TXD7) 66(TXD6) 67(TXD5) 68(TXD4) 84(NC.84) 85(CLK_TO_MAC); U100 1(A1) 3(A2) 4(A3)

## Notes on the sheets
sheet 48
- ER44
sheet 50
- FILTERS
- USB2 / USB3: DLW21SN670HQ2 or DLW21SN121HQ2
- ESD
- USB2: TPD4S012DRY replace with TPD4S014 (TPD4S014-Q1)
- ER17
- FILTERS
- USB2 / USB3: DLW21SN670HQ2 or DLW21SN121HQ2
- ESD
- USB2: TPD4S012DRY replace with TPD4S014 (TPD4S014-Q1)
  USB3:  TPD4EUSB30 replace with two TPD2EUSB30 (TPD2EUSB30-Q1) in drt package
sheet 51
- REV D
sheet 52
- DIR=H : A to B
  DIR=L : B to A
- L = B TO A
  H = A TO B
- L = B TO A
  H = A TO B
- DR26
- L = B TO A
  H = A TO B
sheet 53
- Antenna
sheet 54
- REV D
- VOUT = 0.8 * ( 1+(RTOP/RBOTTOM) )
- 3.6 = 0.8 * ( 1+(RTOP/RBOTTOM ))
- 4.5 = ( 1+(RTOP/RBOTTOM ))
- 3.5 = ((RTOP/RBOTTOM ))
- 3.5 RBOTTOM = RTOP
sheet 55
- ER24
- CENTER TO CENTER SPACING CAN BE
  0.425 INCHES FOR CABLES
sheet 56
- ER47
- PHY ADDR 0x02
- ER8
sheet 57
- ER47
- PHY ADDR 0x03
- ER8
sheet 58
- DIFFERENTIAL PAIR
  100 OHM DIFFERENTIAL
  IMPEDANCE
  SHORT AND STRAIGHT AS
  POSSIBLE,
  MINIMUM NUMBER OF VIAS
